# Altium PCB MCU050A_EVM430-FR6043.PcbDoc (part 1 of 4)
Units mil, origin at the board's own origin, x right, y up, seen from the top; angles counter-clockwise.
Board outline 6000 x 4000 mil, 4 copper layers (Top Layer, GND, PWR, Bottom Layer), stack 61.2 mil thick; 337 components, 255 nets, 1099 pads, 437 vias.
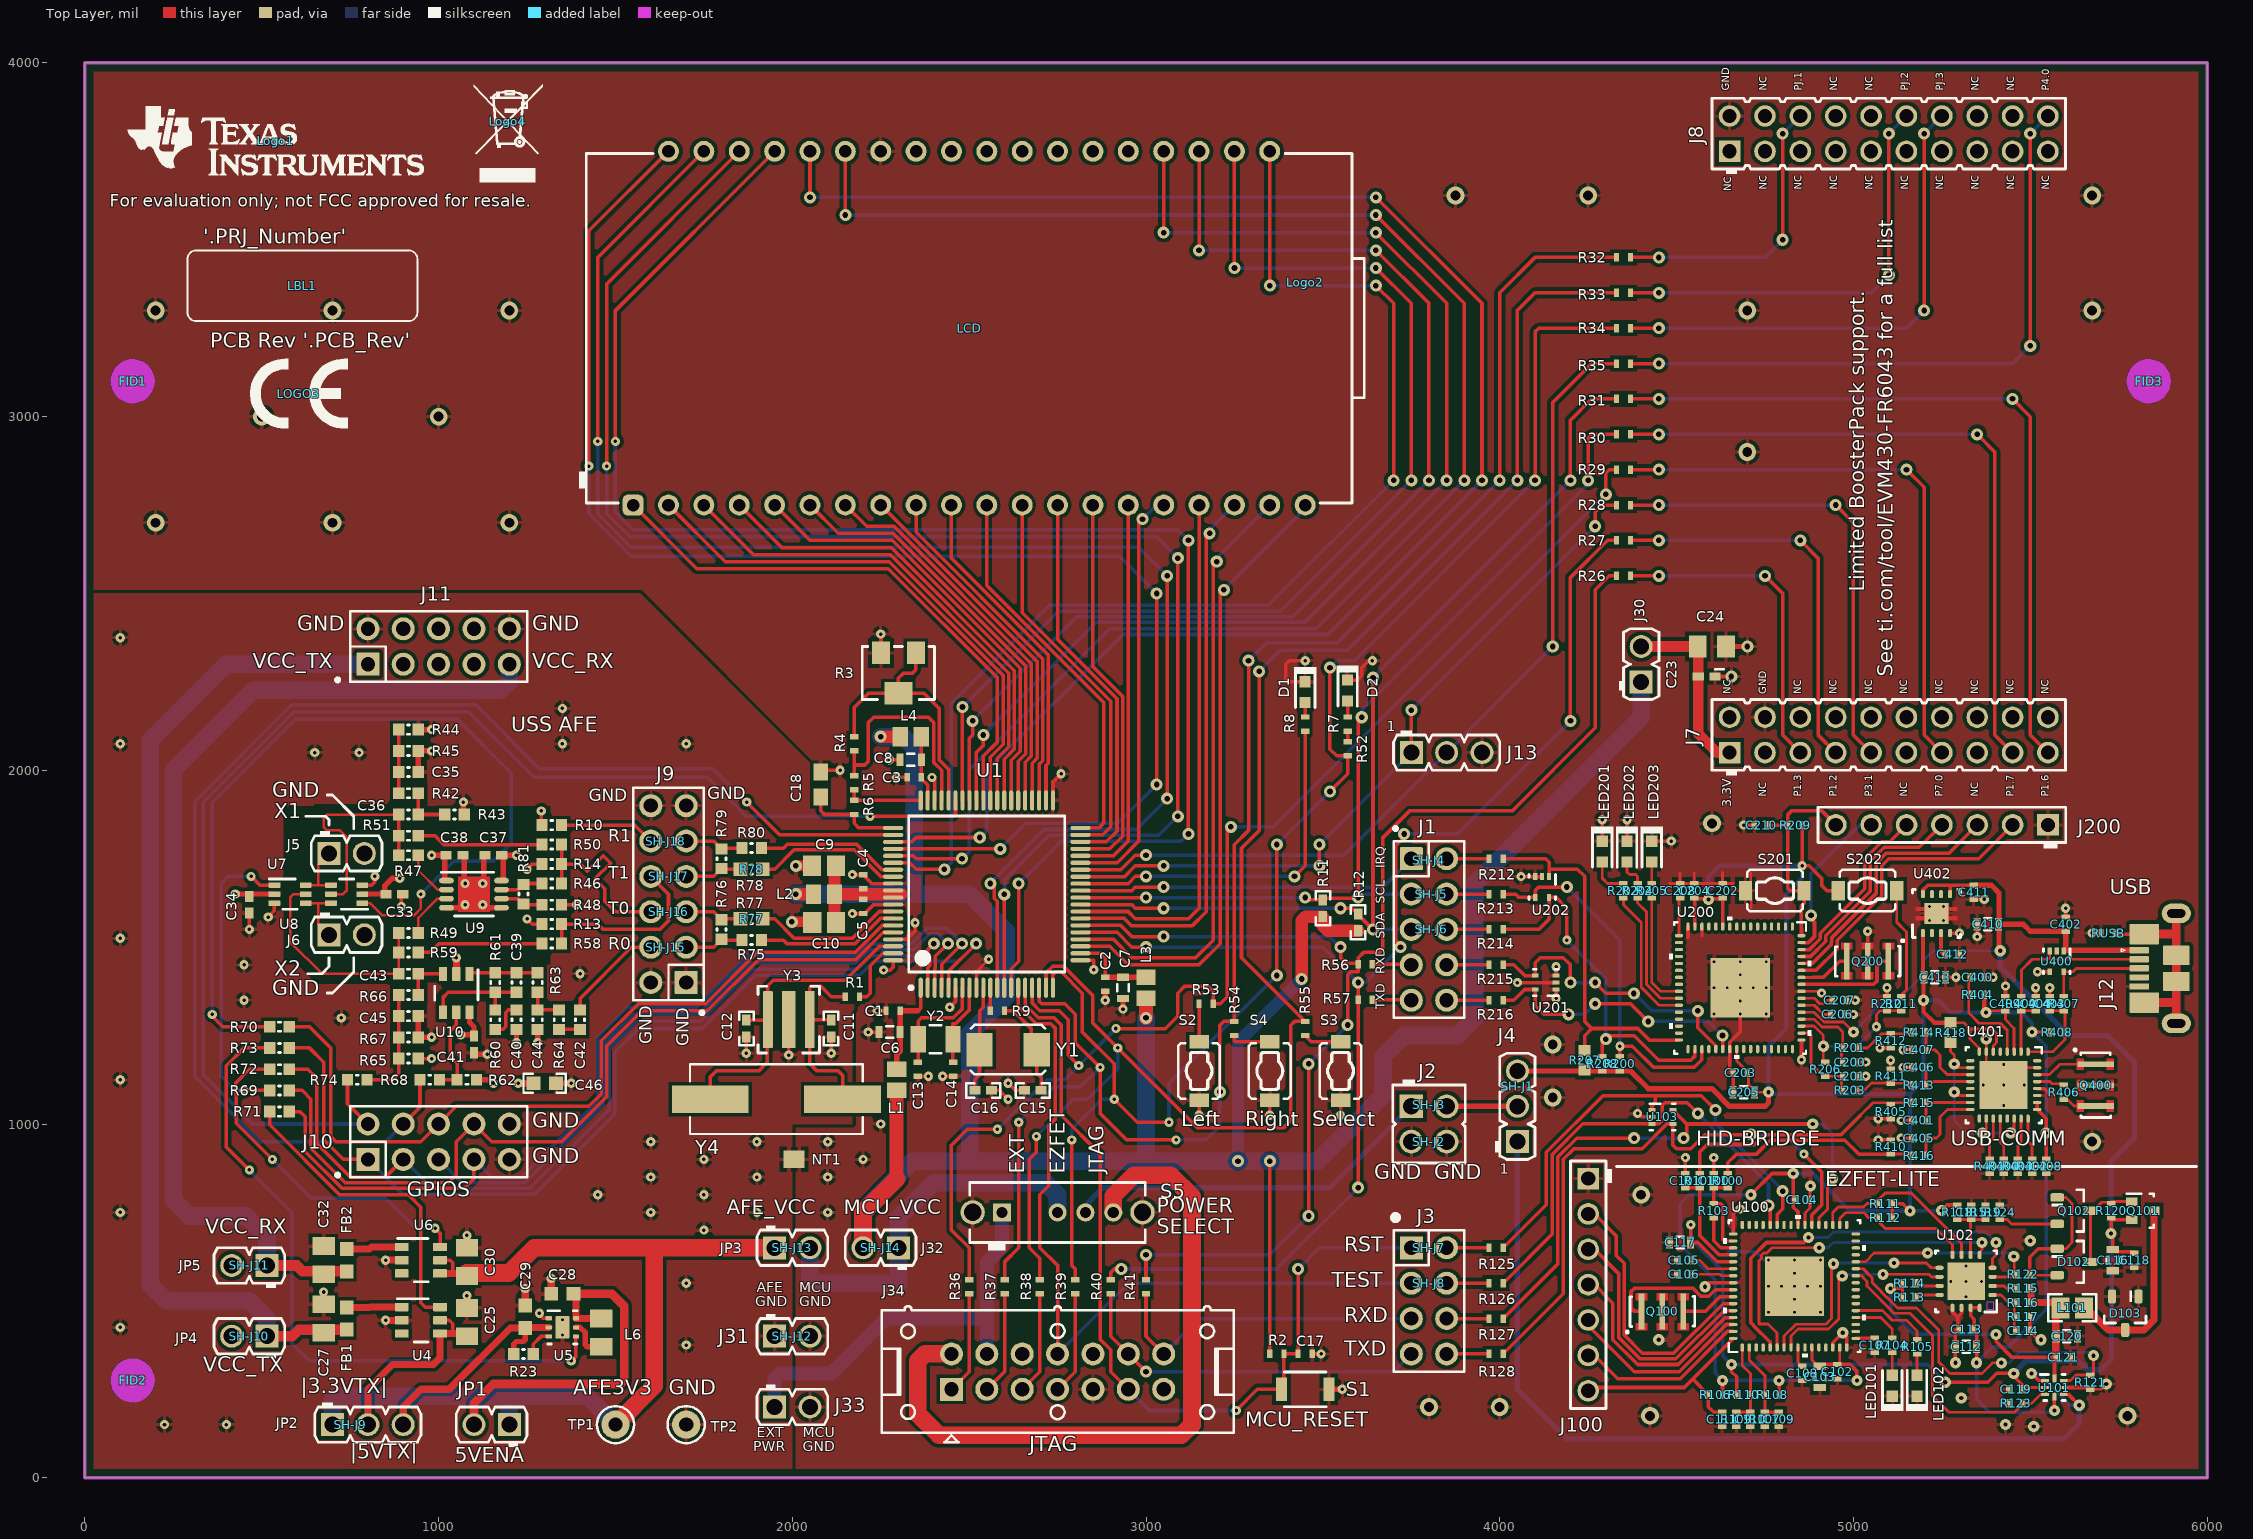
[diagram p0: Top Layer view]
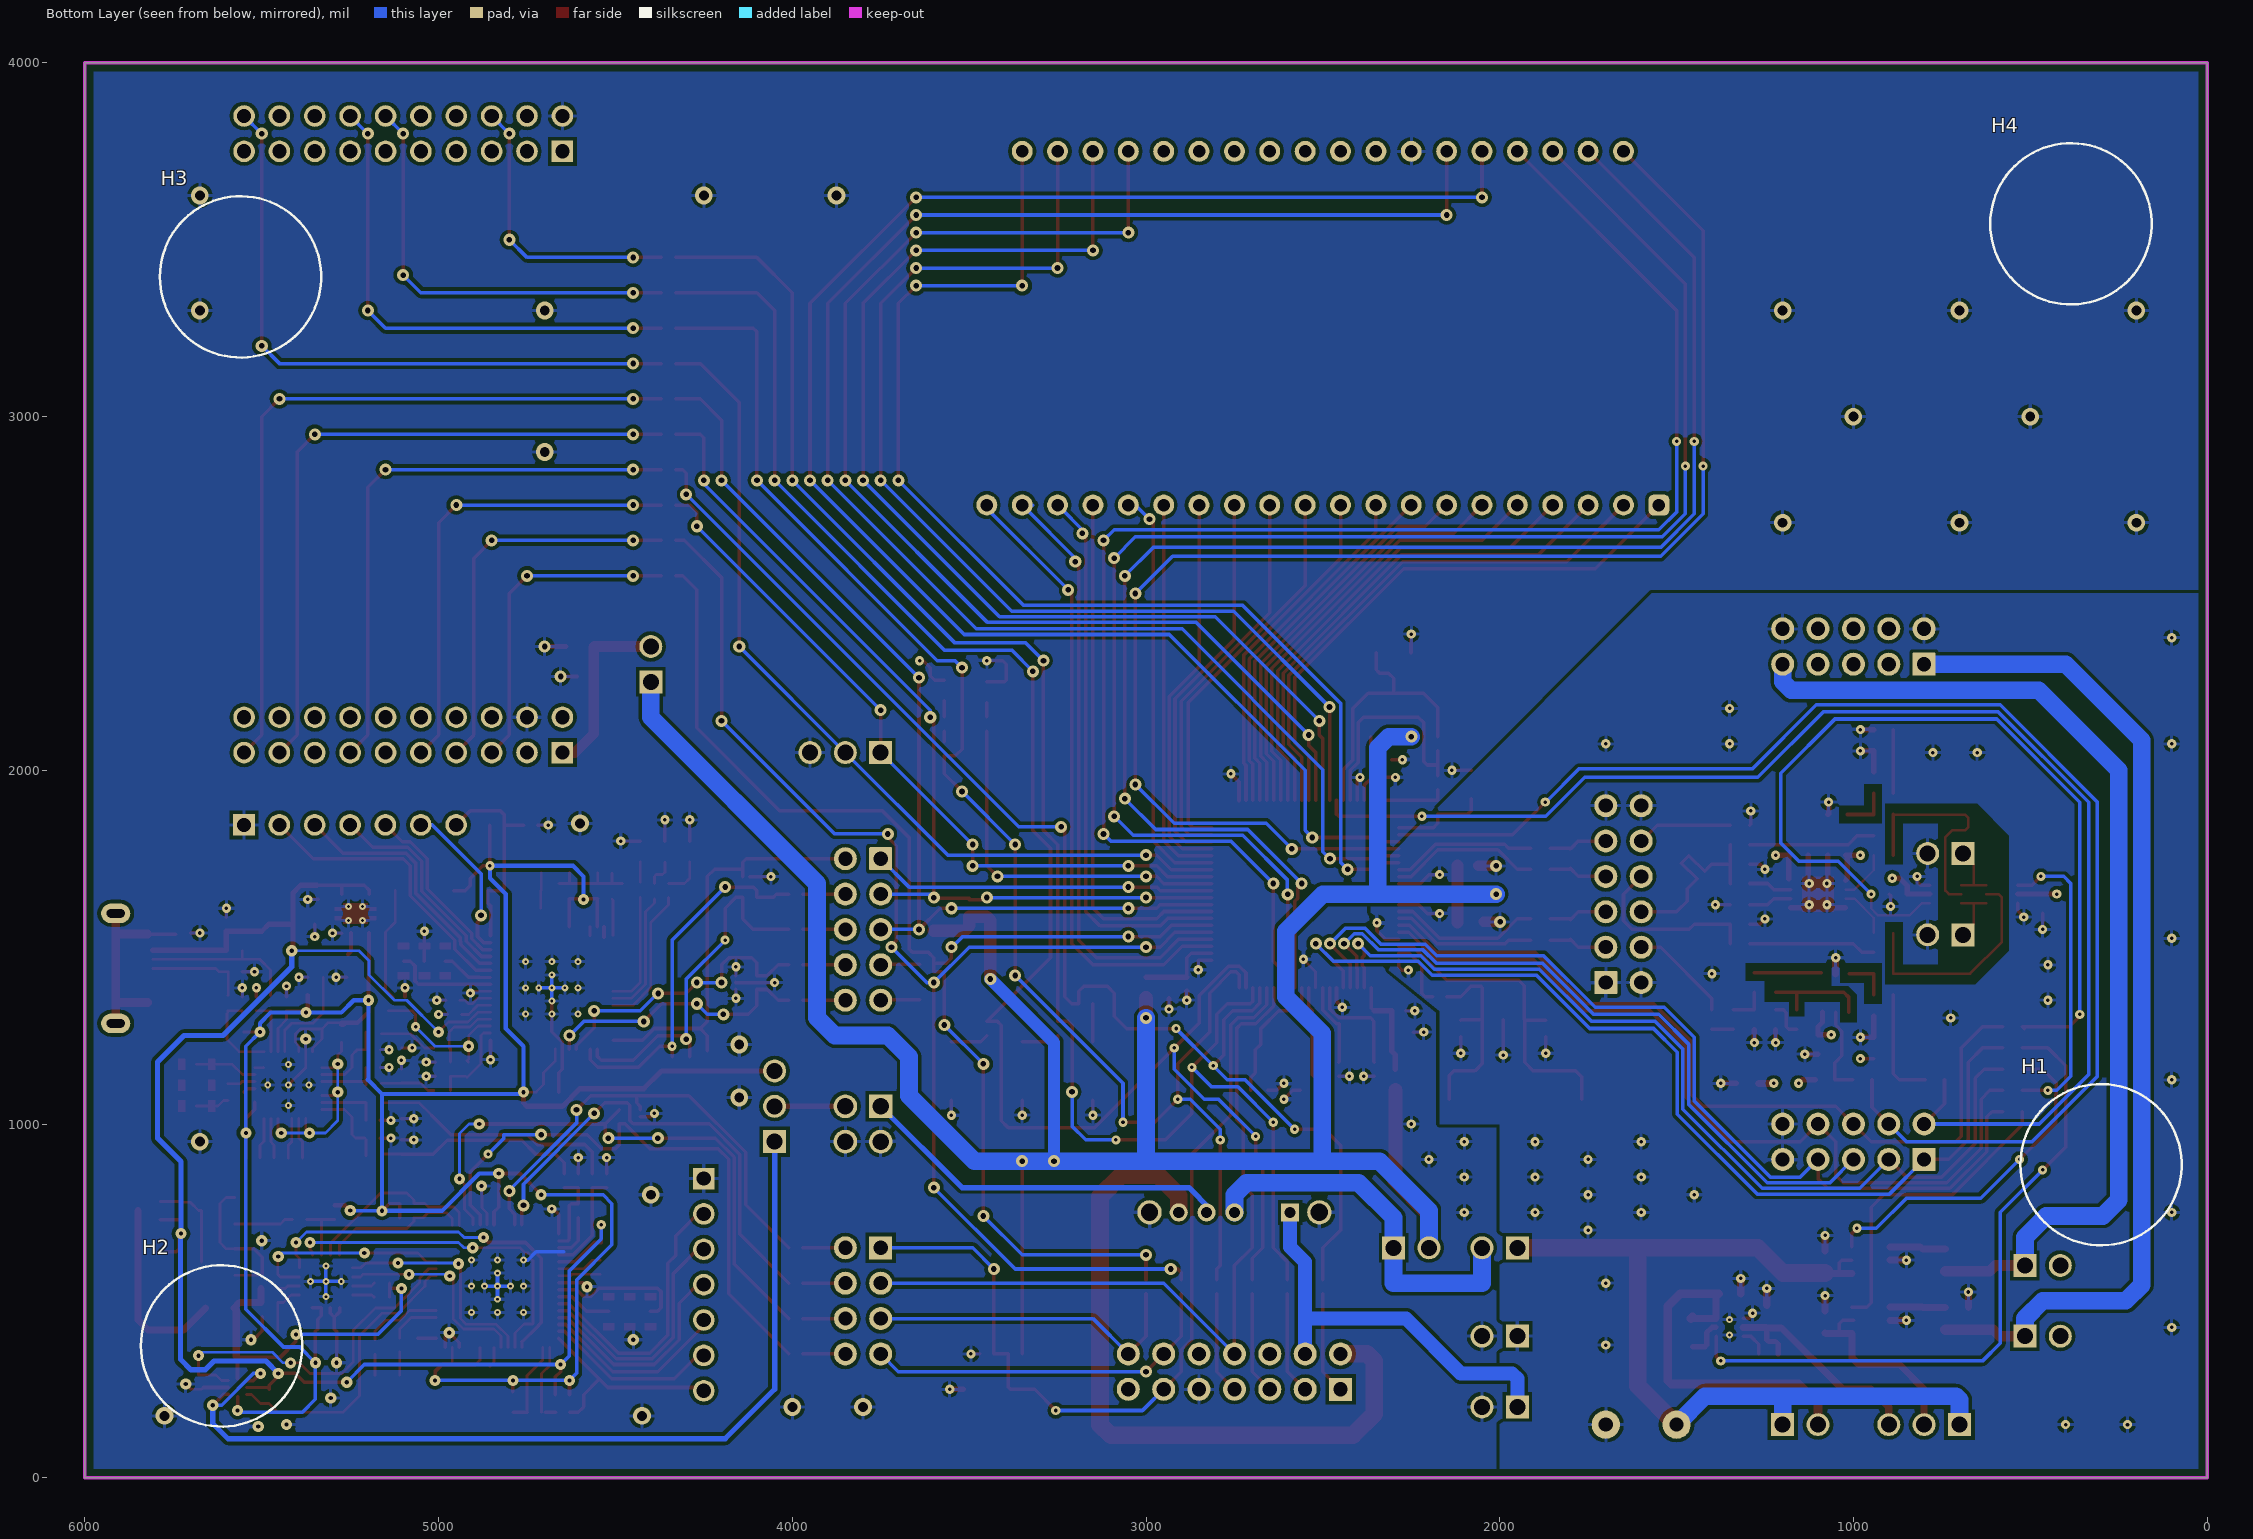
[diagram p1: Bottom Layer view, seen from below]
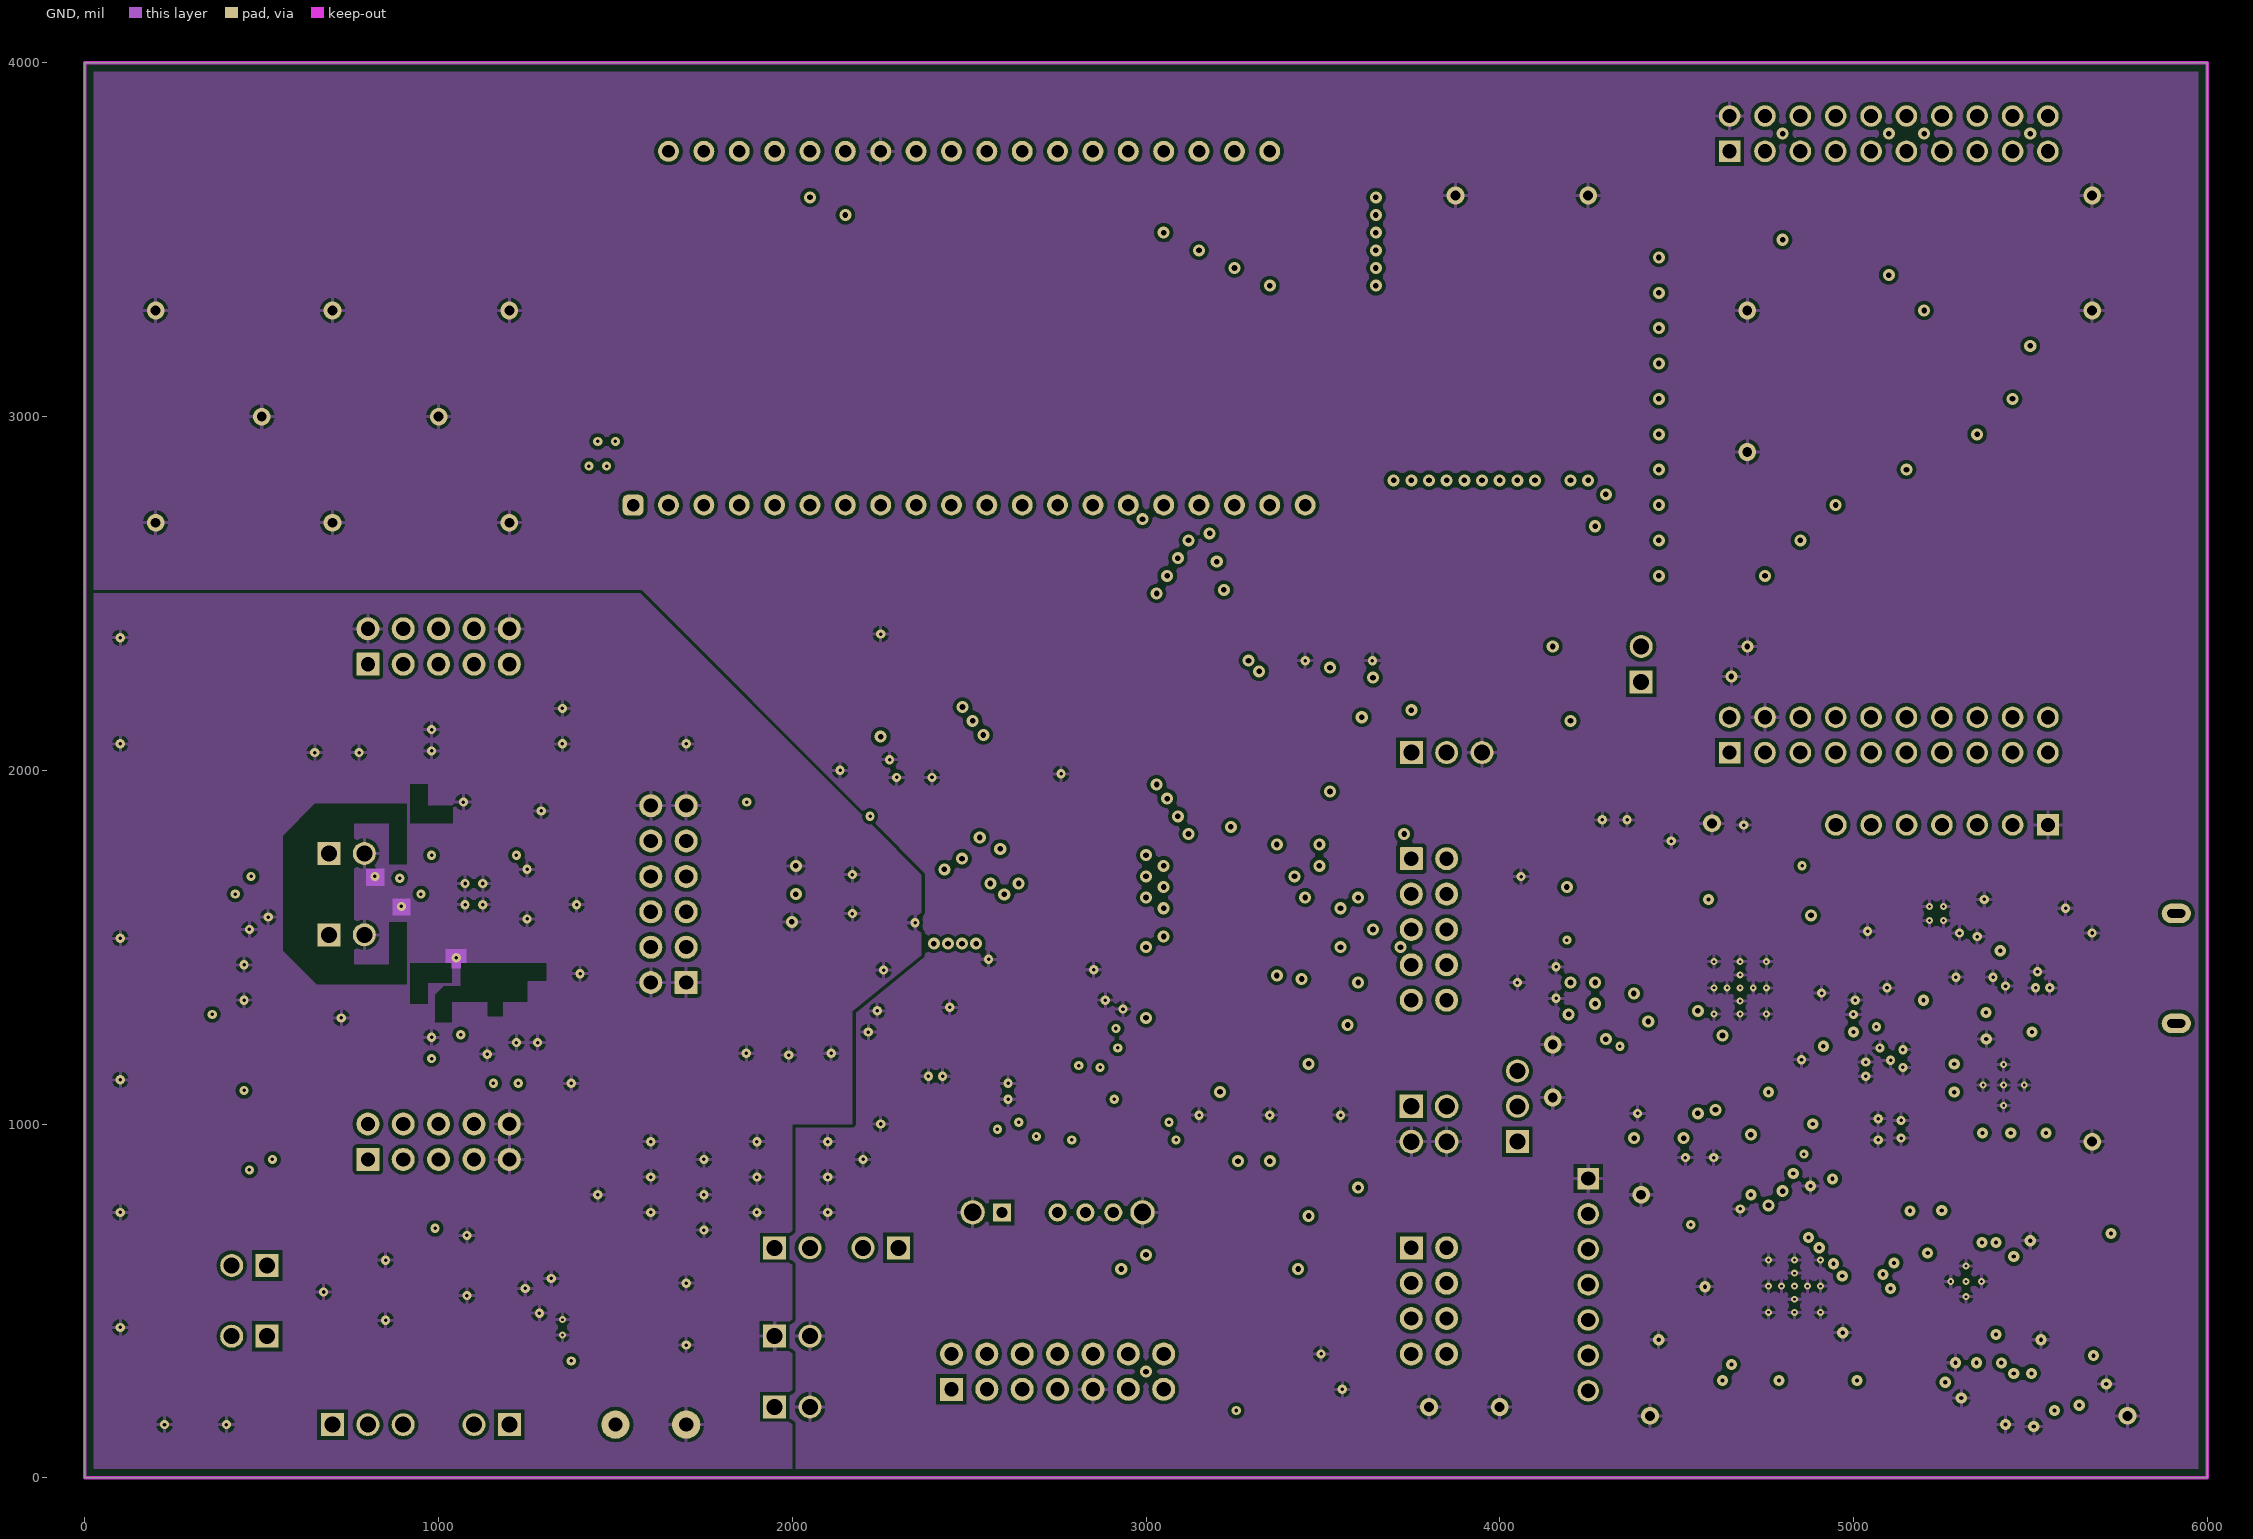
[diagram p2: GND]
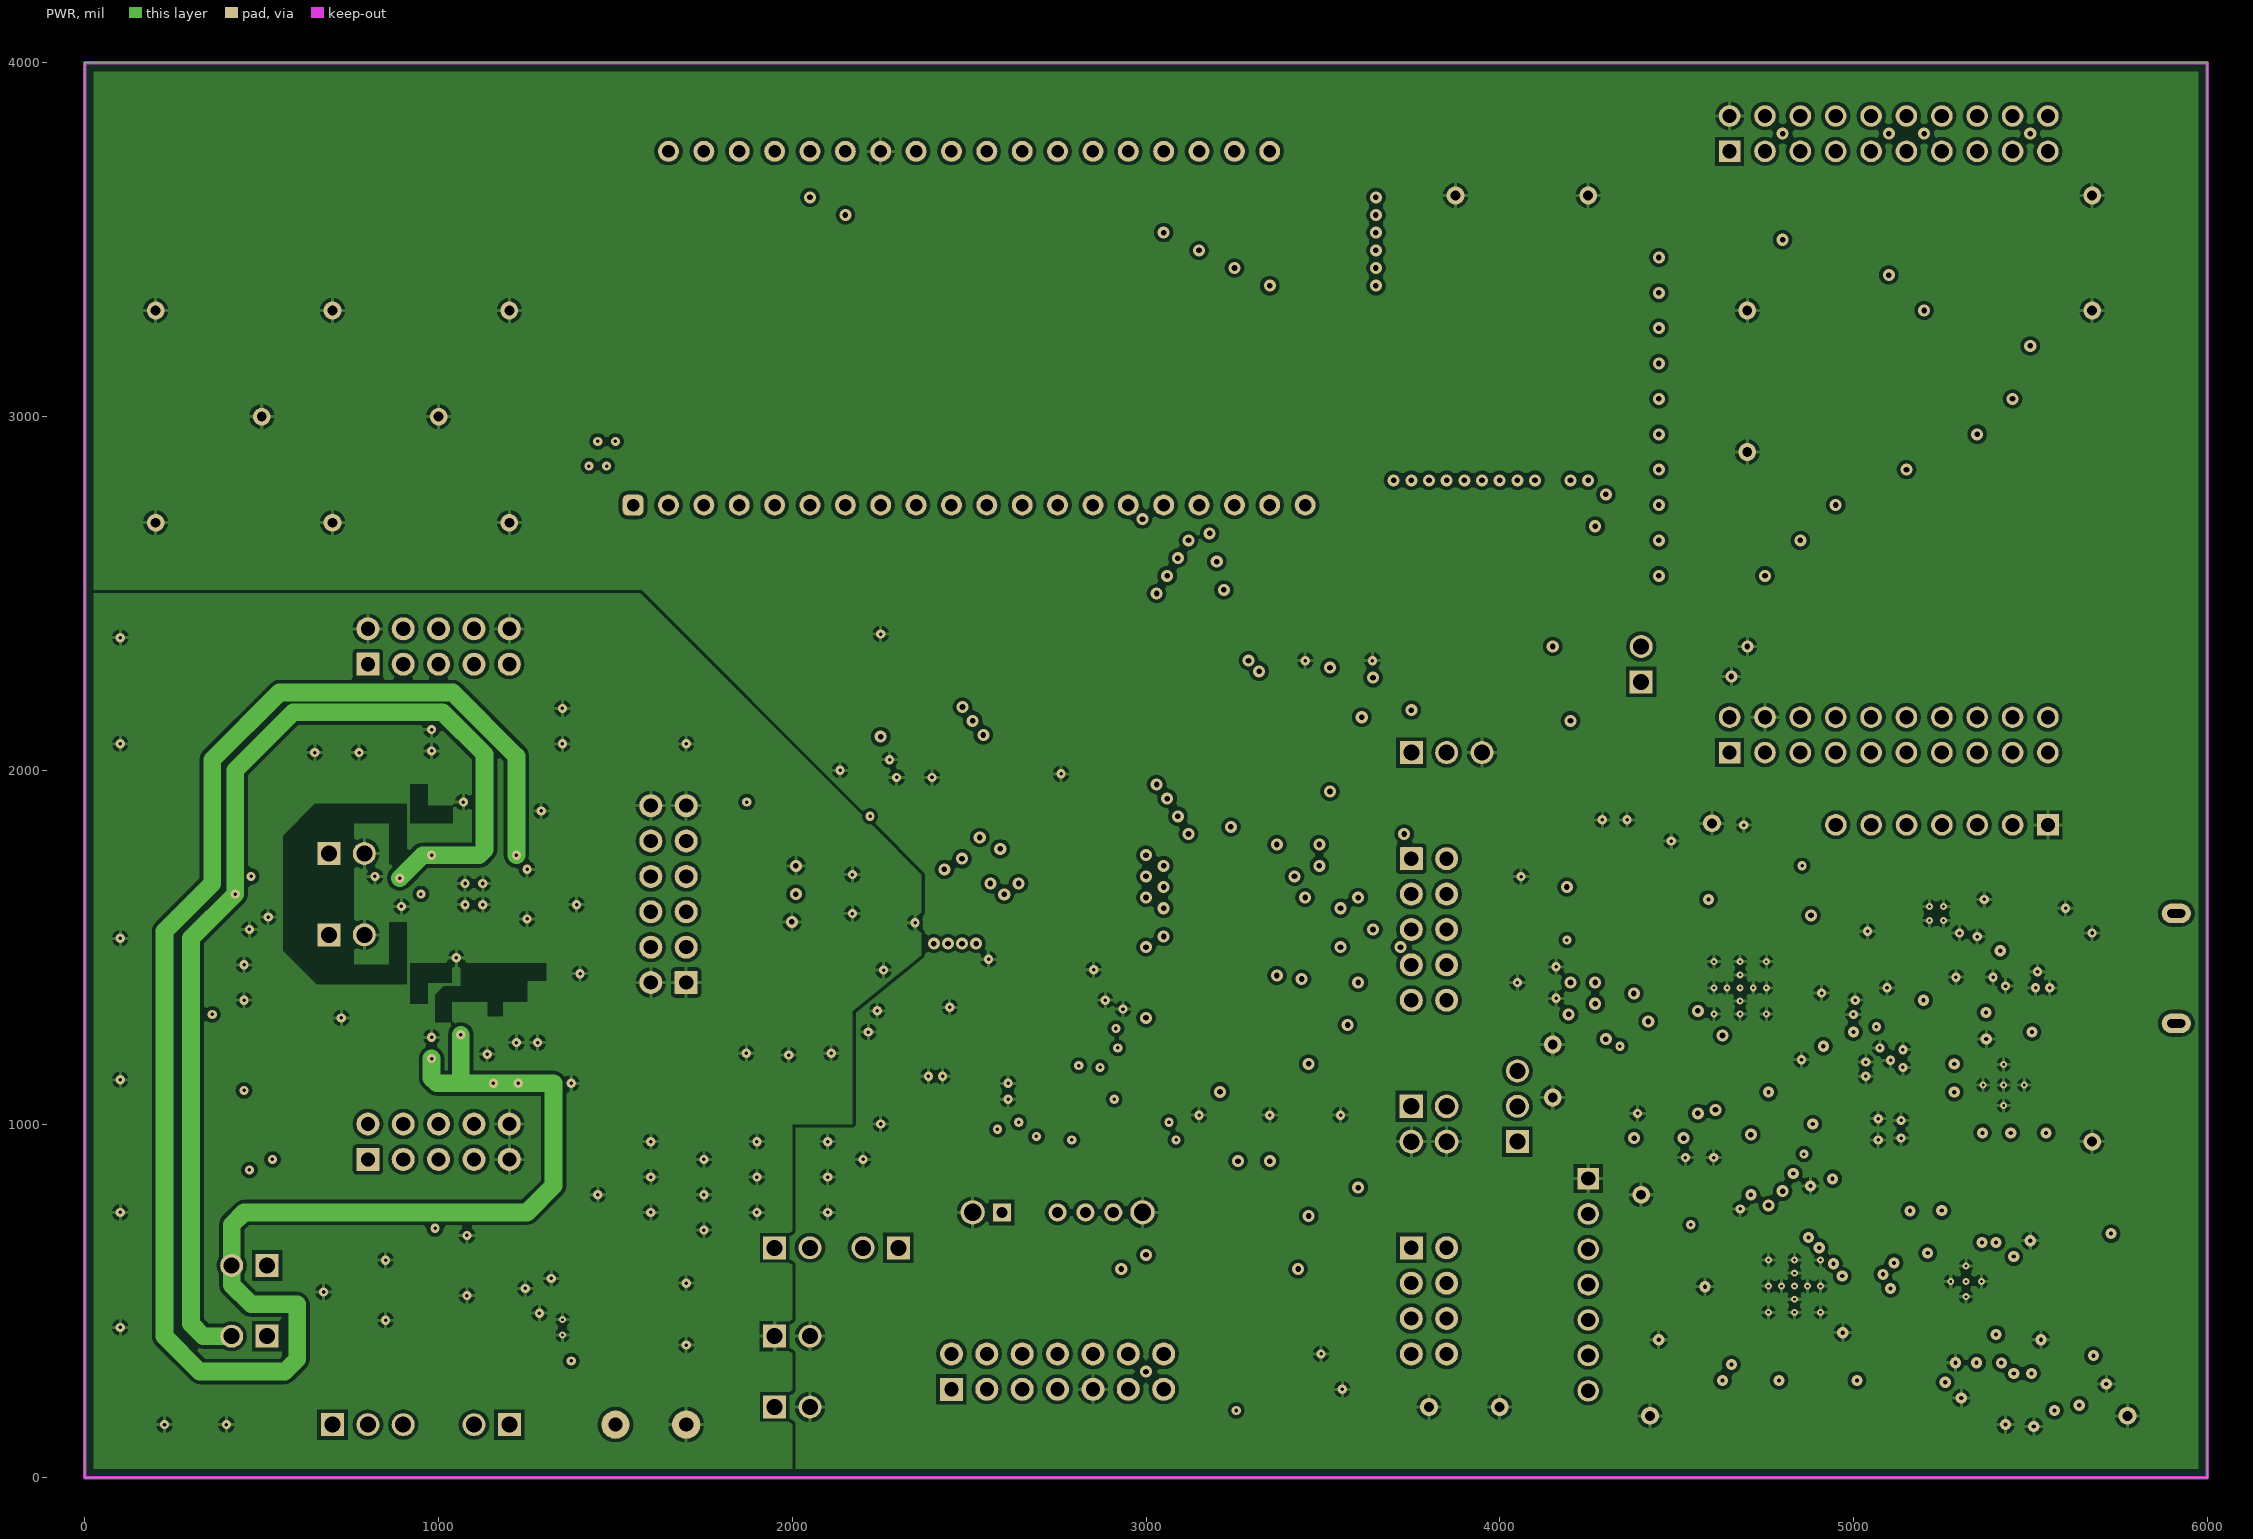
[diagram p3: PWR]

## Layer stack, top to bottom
Top Solder: solder mask 0.4, Solder Resist, Dk 3.5
Top Layer: signal copper 1.4
Dielectric1: core 4.4, FR-4, Dk 4.2
GND: signal copper 0.7
Dielectric 2: core 48.2, FR-4, Dk 4.2
PWR: signal copper 0.7
Dielectric 3: core 4.4, FR-4, Dk 4.2
Bottom Layer: signal copper 1.4
Bottom Solder: solder mask 0.4, Solder Resist, Dk 3.5

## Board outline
0,0 6000,0 6000,4000 0,4000

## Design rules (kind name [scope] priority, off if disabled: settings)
AcuteAngle [All] p1: minimum=4.50000000000000E+0001 checktracksonly=TRUE
AssemblyTestPointUsage [All] p1: valid=2
BoardOutlineClearance BoardOutlineClearance_MountingHoles [OnCopper and InComponentClass('Mounting Holes')] p1: gap=40 ignorepadtopadclearanceinfootprint=FALSE
BoardOutlineClearance BoardOutlineClearance_Poly [OnCopper and IsPoly] p2: gap=25 ignorepadtopadclearanceinfootprint=FALSE
BoardOutlineClearance [OnCopper and Not InComponentClass('Logo') and not InComponentClass('FiducialMark') and not InRegion(1000,500,4000,800) and not InPoly] p3: gap=75 ignorepadtopadclearanceinfootprint=FALSE except(45: SMDPad-OutlineEdge THPad-OutlineEdge; 70: Track-OutlineEdge)
Clearance Clearance_Fiducial [HasFootprint('Fiducial10-30')] p1: gap=0 ignorepadtopadclearanceinfootprint=FALSE
Clearance Clearance_12 [InNamedPolygon('TOP_LAYER_TARGET_GND_P004')] p2: gap=8 ignorepadtopadclearanceinfootprint=FALSE except(0: Arc-Hole Track-Hole SMDPad-Hole THPad-Hole Via-Hole Fill-Hole Poly-Hole Region-Hole Text-Hole)
Clearance Clearance_11 [InNamedPolygon('TOP_LAYER_TARGET_GND_P004')] p3: gap=8 ignorepadtopadclearanceinfootprint=FALSE except(0: Arc-Hole Track-Hole SMDPad-Hole THPad-Hole Via-Hole Fill-Hole Poly-Hole Region-Hole Text-Hole)
Clearance Clearance_10 [InNamedPolygon('TOP_LAYER_TARGET_GND_P004')] p4: gap=8 ignorepadtopadclearanceinfootprint=FALSE except(0: Arc-Hole Track-Hole SMDPad-Hole THPad-Hole Via-Hole Fill-Hole Poly-Hole Region-Hole Text-Hole)
Clearance Clearance_9 [InNamedPolygon('TOP_LAYER_TARGET_GND_P004')] p5: gap=8 ignorepadtopadclearanceinfootprint=FALSE except(0: Arc-Hole Track-Hole SMDPad-Hole THPad-Hole Via-Hole Fill-Hole Poly-Hole Region-Hole Text-Hole)
Clearance Clearance_8 [InNamedPolygon('TOP_LAYER_TARGET_GND_P004')] p6: gap=8 ignorepadtopadclearanceinfootprint=FALSE except(0: Arc-Hole Track-Hole SMDPad-Hole THPad-Hole Via-Hole Fill-Hole Poly-Hole Region-Hole Text-Hole)
Clearance Clearance_7 [InNamedPolygon('TOP_LAYER_TARGET_GND_P004')] p7: gap=10 ignorepadtopadclearanceinfootprint=FALSE except(0: Arc-Hole Track-Hole SMDPad-Hole THPad-Hole Via-Hole Fill-Hole Poly-Hole Region-Hole Text-Hole)
Clearance Clearance_6 [InNamedPolygon('TOP_LAYER_USS_GND_P002')] p8: gap=8 ignorepadtopadclearanceinfootprint=FALSE except(0: Arc-Hole Track-Hole SMDPad-Hole THPad-Hole Via-Hole Fill-Hole Poly-Hole Region-Hole Text-Hole)
Clearance Clearance_5 [InNamedPolygon('BOTTOM_LAYER_USS_GND_P000')] p9: gap=8 ignorepadtopadclearanceinfootprint=FALSE except(0: Arc-Hole Track-Hole SMDPad-Hole THPad-Hole Via-Hole Fill-Hole Poly-Hole Region-Hole Text-Hole)
Clearance Clearance_4 [InNamedPolygon('TARGET_GND_BL')] p10: gap=10 ignorepadtopadclearanceinfootprint=FALSE except(0: Arc-Hole Track-Hole SMDPad-Hole THPad-Hole Via-Hole Fill-Hole Poly-Hole Region-Hole Text-Hole)
Clearance Clearance_3 [InNamedPolygon('TARGET_GND_TL')] p11: gap=10 ignorepadtopadclearanceinfootprint=FALSE except(0: Arc-Hole Track-Hole SMDPad-Hole THPad-Hole Via-Hole Fill-Hole Poly-Hole Region-Hole Text-Hole)
Clearance Clearance_2 [InNamedPolygon('TARGET_GND_BL')] p12: gap=6 ignorepadtopadclearanceinfootprint=FALSE except(0: Arc-Hole Track-Hole SMDPad-Hole THPad-Hole Via-Hole Fill-Hole Poly-Hole Region-Hole Text-Hole)
Clearance Clearance_1 [InNamedPolygon('TARGET_GND_BL')] p13: gap=10 ignorepadtopadclearanceinfootprint=FALSE except(0: Arc-Hole Track-Hole SMDPad-Hole THPad-Hole Via-Hole Fill-Hole Poly-Hole Region-Hole Text-Hole)
Clearance Clearance_Keepouts [((IsTrack Or IsArc) And Not InPoly) And IsFree and IsKeepOut vs ((IsTrack Or IsArc) And Not InPoly) And IsFree and IsKeepOut] p14: gap=0 ignorepadtopadclearanceinfootprint=FALSE
Clearance Clearance_Poly [InPolygon] p15: gap=10 ignorepadtopadclearanceinfootprint=FALSE except(0: Arc-Hole Track-Hole SMDPad-Hole THPad-Hole Via-Hole Fill-Hole Poly-Hole Region-Hole Text-Hole)
Clearance [All] p16: gap=6 ignorepadtopadclearanceinfootprint=FALSE except(0: Arc-Hole Track-Hole SMDPad-Hole THPad-Hole Via-Hole Fill-Hole Poly-Hole Region-Hole Text-Hole)
ComponentClearance ComponentClearance_Shunt_Shunt [InComponentClass('Shunt') vs InComponentClass('Shunt')] p1: gap=0 collisioncheckmode=3 verticalgap=0 showdistances=FALSE
ComponentClearance ComponentClearance_MountingHoles_FiducialMarks [InComponentClass('Mounting Holes') vs InComponentClass('FiducialMark')] p2: gap=50 collisioncheckmode=3 verticalgap=10 showdistances=FALSE
ComponentClearance ComponentClearance_Shunt [InComponentClass('Header') vs InComponentClass('Shunt')] p3: gap=0 collisioncheckmode=3 verticalgap=0 showdistances=FALSE
ComponentClearance ComponentClearance_Logo [InComponentClass('Logo')] p4: gap=50 collisioncheckmode=3 verticalgap=10 showdistances=FALSE
ComponentClearance ComponentClearance_ScrewToNut [(HasFootprint('NY PMS 440 0025 PH')) vs (HasFootprint('Keystone_1902C'))] p5: gap=5 collisioncheckmode=3 verticalgap=10 showdistances=FALSE
ComponentClearance ComponentClearance_MountingHoles [InComponentClass('Mounting Holes')] p6: gap=250 collisioncheckmode=3 verticalgap=100000 showdistances=FALSE
ComponentClearance ComponentClearance_SmallPassives [HasFootprint('0201*') or HasFootprint('0402*') or HasFootprint('0508') or HasFootprint('0603*') or HasFootprint('0612') or HasFootprint('0805*') or HasFootprint('0815*') or HasFootprint('0830*') or HasFootprint('1206*') or HasFootprint('1210*') or HasFootprint('1808*') or HasFootprint('1812*') or HasFootprint('1825*') or HasFootprint('2010*') or HasFootprint('2220*') or HasFootprint('2225*') or HasFootprint('2512*') or HasFootprint('2728*') or HasFootprint('3518*') vs HasFootprint('0201*') or HasFootprint('0402*') or HasFootprint('0508') or HasFootprint('0603*') or HasFootprint('0612') or HasFootprint('0805*') or HasFootprint('0815*') or HasFootprint('0830*') or HasFootprint('1206*') or HasFootprint('1210*') or HasFootprint('1808*') or HasFootprint('1812*') or HasFootprint('1825*') or HasFootprint('2010*') or HasFootprint('2220*') or HasFootprint('2225*') or HasFootprint('2512*') or HasFootprint('2728*') or HasFootprint('3518*')] p7: gap=14.96 collisioncheckmode=3 verticalgap=10 showdistances=FALSE
ComponentClearance ComponentClearance_THtoSMT [IsThruComponent vs IsSMTComponent] p8: gap=25 collisioncheckmode=3 verticalgap=30 showdistances=FALSE
ComponentClearance ComponentClearance_THtoTH [IsThruComponent vs IsThruComponent] p9: gap=30 collisioncheckmode=3 verticalgap=30 showdistances=FALSE
ComponentClearance [All] p10: gap=30 collisioncheckmode=3 verticalgap=10 showdistances=FALSE
DiffPairsRouting [All] p1: maxlimit=100 minlimit=10 mostfreqgap=10 toplayer_minwidth=15 toplayer_maxwidth=15 toplayer_prefwidth=15 midlayer1_minwidth=15 midlayer1_maxwidth=15 midlayer1_prefwidth=15 midlayer2_minwidth=15 midlayer2_maxwidth=15 midlayer2_prefwidth=15 bottomlayer_minwidth=15 bottomlayer_maxwidth=15 bottomlayer_prefwidth=15 maxuncoupledlength=1000
FabricationTestPointUsage TestPointUsage [All] p1: valid=2 allowmultiple=FALSE
FabricationTestpoint Testpoint [All] p1: side=3 testpointundercomponent=TRUE minsize=40 maxsize=100 preferedsize=60 minholesize=0 maxholesize=40 preferedholesize=32 testpointgrid=1 allowsidetop=TRUE allowsidebottom=TRUE usegrid=TRUE gridtolerance=0.01
FanoutControl Fanout_LCC [IsLCC] p1: bgadir=Out bgaviamode=Centered fanoutstyle=Auto fanoutdirection=Alternating viagrid=1 // Fanout_LCC (Default Rule)
FanoutControl Fanout_BGA [IsBGA] p2: bgadir=Out bgaviamode=Centered fanoutstyle=Auto fanoutdirection=Alternating viagrid=1 // Fanout_BGA (Default Rule)
FanoutControl Fanout_Default [All] p4: bgadir=Out bgaviamode=Centered fanoutstyle=Auto fanoutdirection=Alternating viagrid=1 // Fanout_Default (Default Rule)
FanoutControl Fanout_Small [(CompPinCount < 5)] p5: bgadir=Out bgaviamode=Centered fanoutstyle=Auto fanoutdirection=OutThenIn viagrid=1 // Fanout_Small (Default Rule)
HoleSize [All] p1: absolutevalues=TRUE maxlimit=251 minlimit=7.87 maxpercent=80.000 minpercent=20.000
MinimumAnnularRing MinimumAnnularRing_ThermalPadVias [IsVia and InAnyComponent] p1: minimumring=5.91
MinimumAnnularRing [All] p2: minimumring=8
MinimumSolderMaskSliver MinimumSolderMaskSliver_Logo [InComponentClass('Logo') vs InComponentClass('Logo')] p1: minsoldermaskwidth=0.7
MinimumSolderMaskSliver [All] p2: minsoldermaskwidth=3
PlaneConnect [All] p1: planeconnectstyle=Relief reliefexpansion=10 reliefentries=4 reliefconductorwidth=10 reliefairgap=10
PolygonConnect [All] p1: connectstyle=Relief reliefconductorwidth=10 reliefentries=4 polygonreliefangle="90 Angle" airgapwidth=10
RoutingVias ThermalPadVias [IsVia and InAnyComponent] p1: holewidth=7.87 width=19.68 viastyle="Through Hole" minholewidth=7.87 minwidth=19.68 maxholewidth=12.99 maxwidth=23.62
RoutingVias [All] p2: holewidth=16 width=34 viastyle="Through Hole" minholewidth=7.87 minwidth=26 maxholewidth=40 maxwidth=65
SilkToBoardRegionClearance [Not ((IsComment or IsDesignator) And (Hide <> 'False')) and not InRegion(1000,500,4000,800)] p1:
SilkToSilkClearance SilkToSilkClearance_Pb-FreeLogo [(HasFootprint('Pb-Free_Overlay_Medium') OR HasFootprint('Pb-Free_Overlay_Small')) vs (HasFootprint('Pb-Free_Overlay_Medium') OR HasFootprint('Pb-Free_Overlay_Small'))] p1: silktosilkclearance=0
SilkToSilkClearance [All] p2: silktosilkclearance=4
SilkToSolderMaskClearance SilkToComponentPadClearance [(IsPad or IsFill or IsRegion) and InAnycomponent] p1: minsilkscreentomaskgap=3 clearancetoexposedcopper=TRUE
SilkToSolderMaskClearance "Silk to Solder Mask Opening" [All] p2: minsilkscreentomaskgap=4 clearancetoexposedcopper=FALSE
SolderMaskExpansion [All] p1: expansion=1.97
Width PWR [InNetClass('Power_Nets')] p1: maxlimit=50 minlimit=8 preferedwidth=10 midlayer1_minwidth=10 midlayer1_maxwidth=10 midlayer2_minwidth=10 midlayer2_maxwidth=10 minimp=50.000000 maximp=50.000000 favimp=50.000000
Width [All] p2: maxlimit=100 minlimit=6 preferedwidth=10 checkconnectedcopper=TRUE
15 further rules are at their usual default settings.

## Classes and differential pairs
component class FiducialMark: FID1 FID2 FID3
component class Shunt: SH-10 SH-J1 SH-J2 SH-J3 SH-J4 SH-J5 SH-J6 SH-J7 SH-J8 SH-J9 SH-J10 SH-J11 SH-J12 SH-J13 SH-J14 SH-J15 SH-J16 SH-J17 SH-J18
component class AFE: 6 C25 C27 C28 C29 C30 C32 C33 C34 C35 C36 C37 C38 C39 C40 C41 C42 C43 C44 C45 C46 FB1 FB2 J5 J6 J9 J10 J11 JP1 JP2 JP3 JP4 JP5 L6 R10 R13 R14 R23 R42 R43 R44 R45 R46 R47 R48 R49 R50 R51 R58 R59 R60 R61 R62 R63 R64 R65 R66 R67 R68 R69 R70 R71 R72 R73 R74 R75 R76 R77 R78 R79 R80 R81 TP1 TP2 U4 U5 U6 U7 U8 U9 U10
net class Power_Nets: BOOSTER_VCC EXT_VCC EZ-FET_VCC EZFET_TARGET_VCC EZFET_VCCTARGET JTAG_VCC MCU_VCC TARGET_VCC USB_LDO USB_VBUS
component class Logo: Logo1
component class U_EVM430-FR6043_HW: FID1 FID2 FID3 H1 H2 H3 H4 LBL1 Logo1 Logo2 LOGO3 Logo3 Logo4 SH-J1 SH-J2 SH-J3 SH-J4 SH-J5 SH-J6 SH-J7 SH-J8 SH-J9 SH-J10 SH-J11 SH-J12 SH-J13 SH-J14 SH-J15 SH-J16 SH-J17 SH-J18 ZZ1 ZZ2 ZZ3 ZZ4
component class AssemblyNote: ZZ1 ZZ2 ZZ3 ZZ4
component class MCU050A_EVM430-FR6043: J1 J2 J3 J4 J12 R125 R126 R127 R128 R212 R213 R214 R215 R216 RUSB
component class ezFET: C100 C101 C102 C103 C104 C105 C106 C107 C108 C109 C110 C111 C112 C113 C114 C115 C116 C117 C118 C119 C120 C121 D102 D103 J100 L101 LED101 LED102 Q100 Q101 Q102 R100 R101 R103 R104 R105 R106 R107 R108 R109 R110 R111 R112 R113 R114 R115 R116 R117 R118 R119 R120 R121 R122 R123 R124 U100 U101 U102 U103
component class Header: J0 J1 J2 J3 J4 J5 J6 J7 J8 J9 J10 J11 J13 J30 J31 J32 J33 J100 J200 JP1 JP2 JP3 JP4 JP5
component class "HID Bridge": C200 C201 C202 C203 C204 C205 C206 C207 C208 C210 J200 LED201 LED202 LED203 Q200 R200 R201 R202 R203 R204 R205 R206 R207 R208 R209 R210 R211 S201 S202 U200 U201 U202
component class Main: C1 C2 C3 C4 C5 C6 C7 C8 C9 C10 C11 C12 C13 C14 C15 C16 C17 C18 C23 C24 D1 D2 J0 J7 J8 J13 J30 J31 J32 J33 J34 L1 L2 L3 L4 LCD NT1 R1 R2 R3 R4 R5 R6 R7 R8 R9 R11 R12 R26 R27 R28 R29 R30 R31 R32 R33 R34 R35 R36 R37 R38 R39 R40 R41 R52 R53 R54 R55 R56 R57 S1 S2 S3 S4 S5 U1 Y1 Y2 Y3 Y4
component class "USB Hub": C400 C401 C402 C403 C404 C405 C406 C407 C408 C409 C410 C411 C412 C413 Q400 R400 R401 R402 R403 R404 R405 R406 R407 R408 R409 R410 R411 R412 R413 R414 R415 R416 R418 U400 U401 U402
component class Label: LBL1

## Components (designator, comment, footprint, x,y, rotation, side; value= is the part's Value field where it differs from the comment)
C1 "GRM155R71C104KA88D" 0402S 2285,1320 r180 top value=0.1uF
C2 "GRM155R71C104KA88D" 0402S 2885,1395 r90 top value=0.1uF
C3 "GRM155R71C104KA88D" 0402S 2345,1980 r180 top value=0.1uF
C4 "GRM1555C1H102JA01D" 0402S 2200,1685 r270 top value=1000pF
C5 "GRM1555C1H102JA01D" 0402S 2200,1615 r270 top value=1000pF
C6 "GRM188R71A105KA61D" 0603S 2275,1260 r180 top value=1uF
C7 "GRM188R71A105KA61D" 0603S 2935,1385 r90 top value=1uF
C8 "GRM188R71A105KA61D" 0603S 2335,2030 r0 top value=1uF
C9 "C2012X5R1A336M125AC" 0805 2089.69,1730 r0 top value=33uF
C10 "C2012X5R1A336M125AC" 0805 2090,1570 r180 top value=33uF
C11 "GRM1555C1H120JA01D" 0402 2110,1270 r270 top value=12pF
C12 "GRM1555C1H120JA01D" 0402 1870,1270 r270 top value=12pF
C13 "GRM1555C1H120JA01D" 0402S 2355,1155 r270 top value=12pF
C14 "GRM1555C1H120JA01D" 0402S 2455,1155 r90 top value=12pF
C15 "GRM1555C1H120JA01D" 0402 2680,1095 r180 top value=12pF
C16 "GRM1555C1H120JA01D" 0402 2540,1095 r0 top value=12pF
C17 "GRM1555C1H102JA01D" 0402S 3450,350 r0 top value=1000pF
C18 "GRM188R61A475MAAJ" 0603M 2080,1960 r90 top value=4.7uF
C23 "GRM155R71C104KA88D" 0402 4585,2265 r0 top value=0.1uF
C24 "GRM21BR60J476ME15L" 0805_HV 4600,2350 r0 top value=47uF
C25 "GRM219R61A106KE44D" 0805_HV 1079.99,440 r90 top value=10uF
C27 "GRM21BR61C105KA01L" 0805_HV 675,450 r90 top value=1uF
C28 "GRM188R61C225KE15D" 0603 1350,520 r180 top value=2.2uF
C29 "GRM188R61C475KAAJ" 0603 1245,455 r90 top value=4.7uF
C30 "GRM219R61A106KE44D" 0805_HV 1080,610 r90 top value=10uF
C32 "GRM21BR61C105KA01L" 0805_HV 675,615 r90 top value=1uF
C33 "GRM155R71C104KA88D" 0402 875,1650 r180 top value=0.1uF
C34 "GRM155R71C104KA88D" 0402 465,1620 r90 top value=0.1uF
C35 "GRM188R61C225KE15D" 0603L 915,1995 r180 top value=2.2uF
C36 "GRM188R71C105KA12D" 0603L 915,1875 r0 top value=1uF
C37 "GRM155R71C104KA88D" 0402 1155,1760 r180 top value=0.1uF
C38 "GRM155R71C104KA88D" 0402 1045,1760 r180 top value=0.1uF
C39 "GRM1885C1H330JA01D" 0603L 1220,1400 r270 top value=33pF
C40 "GRM188R71C105KA12D" 0603L 1220,1295 r90 top value=1uF
C41 "GRM155R71C104KA88D" 0402 1100,1225 r90 top value=0.1uF
C42 "GRM188R71C102KA01D" 0603L 1400,1295 r270 top value=1000pF
C43 "GRM188R71C105KA12D" 0603L 915,1425 r0 top value=1uF
C44 "GRM1885C1H681JA01D" 0603L 1280,1295 r270 top value=680pF
C45 "GRM188R61C225KE15D" 0603L 915,1305 r180 top value=2.2uF
C46 "GRM188R61C225KE15D" 0603 1300,1115 r0 top value=2.2uF
C100 "GRM1555C1H220JA01D" 0402S 4605,840 r90 top value=22pF
C101 "GRM1555C1H220JA01D" 0402S 4525,840 r90 top value=22pF
C102 "GRM155R71C104KA88D" 0402S 4955,300 r270 top value=0.1uF
C103 "GRM188R61A475MAAJ" 0603S 4905,285 r270 top value=4.7uF
C104 "GRM155R71C104KA88D" 0402S 4853.5,786.39 r0 top value=0.1uF
C105 "GRM155R71C224KA12D" 0402S 4520,615 r180 top value=0.22uF
C106 "GRM155R71C224KA12D" 0402S 4520,575 r180 top value=0.22uF
C107 "GRM155R61C474KE01" 0402S 5060,375 r270 top value=0.47uF
C108 "GRM155R71C104KA88D" 0402S 4855,295 r270 top value=0.1uF
C109 "GRM1555C1H330JA01D" 0402S 4789,165 r270 top value=33pF
C110 "GRM1555C1H330JA01D" 0402S 4709,165 r270 top value=33pF
C111 "GRM1555C1H102JA01D" 0402S 4629,165 r270 top value=1000pF
C112 "GRM188R61A475MAAJ" 0603S 5318.5,370 r180 top value=4.7uF
C113 "GRM155R71C104KA88D" 0402S 5318.5,420 r180 top value=0.1uF
C114 "GRM1555C1H330JA01D" 0402S 5478.5,415 r0 top value=33pF
C115 "GRM1555C1H330JA01D" 0402S 5333.5,750 r90 top value=33pF
C116 "GRM188R61A475MAAJ" 0603S 5733.5,615 r270 top value=4.7uF
C117 "GRM188R61A475MAAJ" 0603S 4510,665 r180 top value=4.7uF
C118 "GRM155R71C104KA88D" 0402S 5793.5,615 r270 top value=0.1uF
C119 "GRM155R71C104KA88D" 0402S 5458.5,250 r180 top value=0.1uF
C120 "GRM188R61A475MAAJ" 0603S 5603.5,400 r0 top value=4.7uF
C121 "GRM155R71C104KA88D" 0402S 5593.5,340 r0 top value=0.1uF
C200 "GRM1555C1H220JA01D" 0402S 4990,1175 r0 top value=22pF
C201 "GRM1555C1H220JA01D" 0402S 4990,1135 r0 top value=22pF
C202 "GRM155R71C104KA88D" 0402S 4630,1660 r90 top value=0.1uF
C203 "GRM155R71C104KA88D" 0402S 4680,1145 r180 top value=0.1uF
C204 "GRM155R71C104KA88D" 0402S 4550,1660 r90 top value=0.1uF
C205 "GRM188R61A475MAAJ" 0603S 4690,1090 r180 top value=4.7uF
C206 "GRM155R71C224KA12D" 0402S 4955,1310 r0 top value=0.22uF
C207 "GRM155R71C224KA12D" 0402S 4960,1350 r0 top value=0.22uF
C208 "GRM155R61C474KE01" 0402S 4510,1660 r90 top value=0.47uF
C210 "GRM1555C1H102JA01D" 0402S 4740,1845 r180 top value=1000pF
C400 "GRM155R71C104KA88D" 0402S 5350,1415 r0 top value=0.1uF
C401 "GRM1555C1H100JA01D" 0402S 5185,1010 r180 top value=10pF
C402 "GRM155R71C104KA88D" 0402S 5600,1565 r90 top value=0.1uF
C403 "GRM1555C1H220JA01D" 0402S 5555,1340 r90 top value=22pF
C404 "GRM1555C1H220JA01D" 0402S 5515,1340 r90 top value=22pF
C405 "GRM1555C1H100JA01D" 0402S 5185,960 r180 top value=10pF
C406 "GRM1555C1H100JA01D" 0402S 5185,1160 r180 top value=10pF
C407 "GRM1555C1H100JA01D" 0402S 5185,1210 r180 top value=10pF
C408 "GRM155R71C104KA88D" 0402S 5545,880 r270 top value=0.1uF
C409 "GRM155R71C104KA88D" 0402S 5430,1340 r90 top value=0.1uF
C410 "GRM188R61A106ME69D" 0603S 5380,1565 r180 top value=10uF
C411 "GRM155R71C104KA88D" 0402S 5340,1655 r270 top value=0.1uF
C412 "GRM155R71C103KA01D" 0402S 5280,1480 r0 top value=0.01uF
C413 "GRM188R61A106ME69D" 0603S 5230,1415 r0 top value=10uF
D1 "LTST-C191TGKT" LTST-C191_Green 3450,2220.83 r90 top value=Green
D2 "LTST-C191TGKT" LTST-C191_Green 3570,2225.41 r90 top value=Green
D102 "BAS40-05-7-F" SOT-23 5623.5,610 r0 top value=40V
D103 "BAS40-05-7-F" SOT-23 5768.5,465 r270 top value=40V
FB1 "MPZ1608S221A" 0603 740,450 r270 top value="220 ohm"
FB2 "MPZ1608S221A" 0603 740,615 r270 top value="220 ohm"
FID1 "Fiducial" Fiducial10-30 135,3100 r0 top
FID2 "Fiducial" Fiducial10-30 135,275 r0 top
FID3 "Fiducial" Fiducial10-30 5835,3100 r0 top
H1 "SJ-5303 (CLEAR)" Bumpon_SJ5003Transparent 300,885 r180 bottom
H2 "SJ-5303 (CLEAR)" Bumpon_SJ5003Transparent 5613.5,372.5 r180 bottom
H3 "SJ-5303 (CLEAR)" Bumpon_SJ5003Transparent 5560,3395 r180 bottom
H4 "SJ-5303 (CLEAR)" Bumpon_SJ5003Transparent 385,3545 r180 bottom
J1 "TSW-105-07-G-D" TSW-105-07-G-D 3800,1550 r270 top
J2 "PBC02DAAN" Sullins_PxC02DAAN 3800,1000 r0 top
J3 "PEC04DAAN" CONN_PEC04DAAN 3800,500 r270 top
J4 "61300311121" WURTH_61300311121 4050,1050 r90 top
J5 "61300211121" WURTH_61300211121 740,1765 r0 top
J6 "61300211121" WURTH_61300211121 740,1535 r0 top
J7 "TSW-110-07-T-D" Samtec_TSW-110-07-x-D 5100,2100 r90 top
J8 "TSW-110-07-T-D" Samtec_TSW-110-07-x-D 5100,3800 r90 top
J9 "TSW-106-07-G-D" TSW-106-07-G-D 1650,1650 r90 top locked
J10 "TSW-105-07-G-D" TSW-105-07-G-D 1000,950 r0 top locked
J11 "TSW-105-07-G-D" TSW-105-07-G-D 1000,2350 r0 top locked
J12 "1051640001" Molex_1051640001 5970,1440 r90 top
J13 "61300311121" WURTH_61300311121 3850,2050 r0 top
J30 "61300211121" WURTH_61300211121 4400,2300 r90 top
J31 "61300211121" WURTH_61300211121 2000,400 r0 top
J32 "61300211121" WURTH_61300211121 2250,650 r180 top
J33 "61300211121" WURTH_61300211121 2000,200 r0 top
J34 "SBH11-PBPC-D07-ST-BK" CONN_SBH11-PBPC-D07-ST-BK 2750,300 r0 top
J100 "PBC07SAAN" Sullins_xxC07SAAN 4250.31,545.79 r270 top
J200 "PBC07SAAN" Sullins_xxC07SAAN 5250.31,1845.79 r180 top
JP1 "61300211121" WURTH_61300211121 1150,150 r180 top
JP2 "61300311121" WURTH_61300311121 800,150 r0 top
JP3 "61300211121" WURTH_61300211121 2000,650 r0 top
JP4 "61300211121" WURTH_61300211121 465,400 r180 top
JP5 "61300211121" WURTH_61300211121 465,600 r180 top
L1 "MPZ2012S601A" 0805L 2295,1125 r270 top value="600 ohm"
L2 "MPZ2012S601A" 0805L 2089.69,1650 r0 top value="600 ohm"
L3 "MPZ2012S601A" 0805L 3000,1385 r270 top value="600 ohm"
L4 "MPZ2012S601A" 0805L 2335,2095 r180 top value="600 ohm"
L6 "LQM21PN1R0MC0D" 0805_HV 1460,410 r90 top value=1uH
L101 "CIG21L2R2MNE" 0805 5618.5,480 r180 top value=2.2uH
LBL1 "THT-14-423-10" Label_650x200 615,3370 r180 top
LCD "FH-1138P" ADKOM_FH-1138P 2500,3250 r90 top
LED101 "LTST-C190CKT" LED_LTST-C190_Red 5110,260 r270 top value=Red
LED102 "LTST-C191TGKT" LTST-C191_Green 5180,260 r270 top value=Green
LED201 "LTST-C191TGKT" LTST-C191_Green 4290,1770 r90 top value=Green
LED202 "LTST-C191TGKT" LTST-C191_Green 4360,1770 r90 top value=Green
LED203 "LTST-C190CKT" LED_LTST-C190_Red 4430,1770 r90 top value=Red
Logo1 "Texas Instruments" TI_Stacked_Overlay_Small 540,3780 r0 top
Logo2 "FCC disclaimer" FCC_disclaimer 3450,3380 r0 top
LOGO3 "CE Mark" CE_Mark_5mm 605,3065 r0 top
Logo4 "WEEE logo" WEEE_Minimum 1195,3835 r0 top
NT1 "Net-Tie" Net-Tie_50milWide_30milLong 2005,900 r0 top net-tie
Q100 "CSTCR4M00G15L99-R0" Murata_CSTCR 4460,470 r0 top
Q101 "DMG1013UW" SOT-323 5818.5,755 r0 top value=-50V
Q102 "BC850CLT1G" SOT-23 5623.5,755 r0 top value=0.7V
Q200 "CSTCR4M00G15L99-R0" Murata_CSTCR 5040,1460 r180 top
Q400 "CSTCR6M00G53Z-R0" Murata_CSTCR 5685,1110 r270 top
R1 "CRCW040222R0JNED" 0402S 2170,1360 r0 top value=22
R2 "CRCW040247K0JNED" 0402S 3370,350 r180 top value=47k
R3 "3224W-1-204E" TRIM_3224W 2300,2275 r270 top value=200k
R4 "CRCW0402330KJNED" 0402S 2175,2075 r90 top value=330k
R5 "CRCW0402330KJNED" 0402S 2175,1965 r270 top value=330k
R6 "CRCW0402330KJNED" 0402S 2175,1895 r270 top value=330k
R7 "CRCW0402390RJNED" 0402S 3570,2130.83 r90 top value=390
R8 "CRCW0402390RJNED" 0402S 3450,2130.83 r90 top value=390
R9 "CRCW040222R0JNED" 0402S 2580,1320 r180 top value=22
R10 "RC0603FR-071ML" 0603L 1320,1845 r0 top value=1.00Meg
R11 "ERJ-2RKF3301X" 0402 3500,1610 r270 top value=3.30k
R12 "ERJ-2RKF3301X" 0402 3600,1570 r270 top value=3.30k
R13 "RC0603FR-071ML" 0603L 1320,1565 r0 top value=1.00Meg
R14 "RC0603FR-071ML" 0603L 1320,1735 r0 top value=1.00Meg
R23 "RC0603JR-070RL" 0603L 1240,350 r0 top value=0
R26 "CRCW04020000Z0ED" 0402S 4350,2550 r0 top value=0
R27 "CRCW04020000Z0ED" 0402S 4350,2650 r0 top value=0
R28 "CRCW04020000Z0ED" 0402S 4350,2750 r0 top value=0
R29 "CRCW04020000Z0ED" 0402S 4350,2850 r0 top value=0
R30 "CRCW04020000Z0ED" 0402S 4350,2950 r0 top value=0
R31 "CRCW04020000Z0ED" 0402S 4350,3050 r0 top value=0
R32 "CRCW04020000Z0ED" 0402S 4350,3450 r0 top value=0
R33 "CRCW04020000Z0ED" 0402S 4350,3350 r0 top value=0
R34 "CRCW04020000Z0ED" 0402S 4350,3250 r0 top value=0
R35 "CRCW04020000Z0ED" 0402S 4350,3150 r0 top value=0
R36 "CRCW04020000Z0ED" 0402S 2500,540 r90 top value=0
R37 "CRCW04020000Z0ED" 0402S 2600,540 r90 top value=0
R38 "CRCW04020000Z0ED" 0402S 2700,540 r90 top value=0
R39 "CRCW04020000Z0ED" 0402S 2800,540 r90 top value=0
R40 "CRCW04020000Z0ED" 0402S 2900,540 r90 top value=0
R41 "CRCW04020000Z0ED" 0402S 3000,540 r90 top value=0
R42 "RC0603FR-0724K9L" 0603L 915,1935 r0 top value=24.9k
R43 "RC0603FR-07200KL" 0603L 1045,1875 r0 top value=200k
R44 "RC0603FR-072ML" 0603L 915,2115 r180 top value=2.00Meg
R45 "RC0603FR-072ML" 0603L 915,2055 r180 top value=2.00Meg
R46 "RC0603JR-070RL" 0603L 1320,1680 r180 top value=0
R47 "RC0603FR-07806RL" 0603L 915,1760 r180 top value=806
R48 "RC0603JR-070RL" 0603L 1320,1620 r180 top value=0
R49 "RC0603FR-07806RL" 0603L 915,1540 r180 top value=806
R50 "RC0603JR-070RL" 0603L 1320,1790 r180 top value=0
R51 "RC0603FR-07806RL" 0603L 915,1815 r180 top value=806
R52 "CRCW04020000Z0ED" 0402S 3570,2060.83 r270 top value=0
R53 "CRCW04020000Z0ED" 0402S 3170,1340 r0 top value=0
R54 "CRCW04020000Z0ED" 0402S 3250,1270 r90 top value=0
R55 "CRCW04020000Z0ED" 0402S 3450,1270 r90 top value=0
R56 "CRCW04020000Z0ED" 0402S 3620,1451.79 r180 top value=0
R57 "CRCW04020000Z0ED" 0402S 3620,1351.79 r180 top value=0
R58 "RC0603JR-070RL" 0603L 1320,1510 r180 top value=0
R59 "RC0603FR-07806RL" 0603L 915,1485 r180 top value=806
R60 "RC0603FR-0710RL" 0603L 1160,1295 r90 top value=10.0
R61 "RC0603FR-071K82L" 0603L 1160,1400 r90 top value=1.82k
R62 "RCG060310K0FKEA" 0603L 1080,1125 r180 top value=10.0k
R63 "RC0603FR-07499RL" 0603L 1280,1400 r270 top value=499
R64 "RC0603JR-070RL" 0603L 1340,1295 r90 top value=0
R65 "RC0603FR-072ML" 0603L 915,1185 r0 top value=2.00Meg
R66 "RC0603FR-0724K9L" 0603L 915,1365 r0 top value=24.9k
R67 "RC0603FR-072ML" 0603L 915,1245 r180 top value=2.00Meg
R68 "RC0603JR-070RL" 0603L 975,1125 r180 top value=0
R69 "RC0603JR-070RL" 0603L 550,1095 r180 top value=0
R70 "RC0603JR-070RL" 0603L 550,1275 r0 top value=0
R71 "RC0603JR-070RL" 0603L 550,1035 r0 top value=0
R72 "RC0603JR-070RL" 0603L 550,1155 r0 top value=0
R73 "RC0603JR-070RL" 0603L 550,1215 r0 top value=0
R74 "RC0603JR-070RL" 0603L 770,1125 r180 top value=0
R75 "RC0603JR-070RL" 0603L 1885,1520 r180 top value=0
R76 "RC0603JR-070RL" 0603L 1800,1550 r270 top value=0
R77 "RC0603FR-07200RL" 0603 1885,1580 r180 top value=200
R77 "RC0603JR-070RL" 0603L 1885,1580 r180 top value=0
R78 "RC0603FR-07200RL" 0603 1885,1720 r180 top value=200
R78 "RC0603JR-070RL" 0603L 1885,1720 r180 top value=0
R79 "RC0603JR-070RL" 0603L 1800,1750 r270 top value=0
R80 "RC0603JR-070RL" 0603L 1885,1780 r180 top value=0
R81 "RCG060310K0FKEA" 0603L 1240,1650 r90 top value=10.0k
R100 "CRCW040222R0JNED" 0402S 4645,840 r270 top value=22
R101 "CRCW040222R0JNED" 0402S 4565,840 r270 top value=22
R103 "CRCW04021K50JNED" 0402S 4605,755 r90 top value=1.5k
R104 "CRCW0402470RJNED" 0402S 5110,375 r90 top value=470
R105 "CRCW0402390RJNED" 0402S 5180,370 r90 top value=390
R106 "CRCW040247K0JNED" 0402S 4610,235 r0 top value=47k
R107 "CRCW0402221KFKED" 0402S 4749,165 r90 top value=221k
R108 "CRCW0402221KFKED" 0402S 4770,235 r0 top value=221k
R109 "CRCW0402150KFKED" 0402S 4669,165 r90 top value=150k
R110 "CRCW0402240KFKED" 0402S 4690,235 r180 top value=240k
R111 "CRCW04024K70JNED" 0402S 5090,775 r180 top value=4.7k
R112 "CRCW04024K70JNED" 0402S 5090,735 r180 top value=4.7k
R113 "CRCW04022K20FKED" 0402S 5158.5,510 r180 top value=2.20k
R114 "CRCW04026K81FKED" 0402S 5158.5,550 r180 top value=6.81k
R115 "CRCW04023K32FKED" 0402S 5478.5,535 r180 top value=3.32k
R116 "CRCW0402221KFKED" 0402S 5478.5,495 r0 top value=221k
R117 "CRCW0402221KFKED" 0402S 5478.5,455 r180 top value=221k
R118 "CRCW0402221KFKED" 0402S 5293.5,750 r270 top value=221k
R119 "CRCW0402221KFKED" 0402S 5373.5,750 r270 top value=221k
R120 "CRCW0402470RJNED" 0402S 5728.5,755 r90 top value=470
R121 "CRCW040247K0JNED" 0402S 5670,270 r90 top value=47k
R122 "CRCW0402820RJNED" 0402S 5478.5,575 r180 top value=820
R123 "CRCW040247K0JNED" 0402S 5458.5,210 r0 top value=47k
R124 "CRCW04020000Z0ED" 0402S 5413.5,750 r90 top value=0
R125 "CRCW0402100RJNED" 0402S 3990,650 r180 top value=100
R126 "CRCW0402100RJNED" 0402S 3990,550 r180 top value=100
R127 "CRCW0402100RJNED" 0402S 3990,450 r180 top value=100
R128 "CRCW0402100RJNED" 0402S 3990,350 r180 top value=100
R200 "CRCW04022K20FKED" 0402S 4340,1170 r270 top value=2.20k
R201 "CRCW040222R0JNED" 0402S 4990,1215 r180 top value=22
R202 "CRCW0402390RJNED" 0402S 4350,1660 r270 top value=390
R203 "CRCW040222R0JNED" 0402S 4990,1095 r180 top value=22
R204 "CRCW0402390RJNED" 0402S 4390,1660 r270 top value=390
R205 "CRCW0402470RJNED" 0402S 4430,1660 r270 top value=470
R206 "CRCW04021K50JNED" 0402S 4920,1155 r90 top value=1.5k
R207 "RCG060310K0FKEA" 0603L 4240,1180 r270 top value=10.0k
R208 "CRCW04022K20FKED" 0402S 4290,1170 r270 top value=2.20k
R209 "CRCW040247K0JNED" 0402S 4835,1845 r0 top value=47k
R210 "CRCW04021M00JNED" 0402S 5095,1340 r270 top value=1.0Meg
R211 "CRCW0402100RJNED" 0402S 5135,1340 r90 top value=100
R212 "CRCW0402100RJNED" 0402S 3990,1750 r180 top value=100
R213 "CRCW0402100RJNED" 0402S 3990,1650 r180 top value=100
R214 "CRCW0402100RJNED" 0402S 3990,1550 r180 top value=100
R215 "CRCW0402100RJNED" 0402S 3990,1450 r180 top value=100
R216 "CRCW0402100RJNED" 0402S 3990,1350 r180 top value=100
R400 "CRCW040215K0JNED" 0402S 5425,880 r270 top value=15k
R401 "CRCW040215K0JNED" 0402S 5385,880 r270 top value=15k
R402 "CRCW040215K0JNED" 0402S 5505,880 r270 top value=15k
R403 "CRCW040215K0JNED" 0402S 5465,880 r270 top value=15k
R404 "CRCW040247K0JNED" 0402S 5350,1365 r0 top value=47k
R405 "CRCW040215K0JNED" 0402S 5105,1035 r90 top value=15k
R406 "CRCW040227R0JNED" 0402S 5595,1090 r90 top value=27
R407 "CRCW040222R0JNED" 0402S 5595,1340 r270 top value=22
R408 "CRCW04021K50JNED" 0402S 5575,1260 r180 top value=1.5k
R409 "CRCW040222R0JNED" 0402S 5475,1340 r270 top value=22
R410 "CRCW040215K0JNED" 0402S 5105,935 r270 top value=15k
R411 "CRCW040215K0JNED" 0402S 5105,1135 r270 top value=15k
R412 "CRCW040215K0JNED" 0402S 5105,1235 r90 top value=15k
R413 "CRCW040222R0JNED" 0402S 5185,1110 r0 top value=22
R414 "CRCW040222R0JNED" 0402S 5185,1260 r0 top value=22
R415 "CRCW040222R0JNED" 0402S 5185,1060 r0 top value=22
R416 "CRCW040222R0JNED" 0402S 5185,910 r0 top value=22
R418 "RCG060310K0FKEA" 0603L 5275,1258.62 r90 top value=10.0k
RUSB "CRCW040233R0JNED" 0402S 5720,1540 r0 top value=33
S1 "B3U-1000P" SW_B3U-1000P 3450,250 r180 top
S2 "TL1015AF160QG" SW_TL1015AF160QG 3150.01,1149.99 r90 top
S3 "TL1015AF160QG" SW_TL1015AF160QG 3550.01,1149.99 r90 top
S4 "TL1015AF160QG" SW_TL1015AF160QG 3350.01,1149.99 r90 top
S5 "SS-13D16-VG 4 PA" SW_SS-13D16-VG 2750,750 r0 top
S201 "TL1015AF160QG" SW_TL1015AF160QG 4777.95,1660 r0 top
S202 "TL1015AF160QG" SW_TL1015AF160QG 5040,1660 r180 top
SH-J1 "60900213421" Wurth_60900213421 4050,1107.15 r90 top
SH-J2 "60900213421" Wurth_60900213421 3800,950 r180 top
SH-J3 "60900213421" Wurth_60900213421 3800,1055 r180 top
SH-J4 "60900213421" Wurth_60900213421 3800,1745 r180 top
SH-J5 "60900213421" Wurth_60900213421 3807.15,1650 r180 top
SH-J6 "60900213421" Wurth_60900213421 3807.15,1550 r180 top
SH-J7 "60900213421" Wurth_60900213421 3800,650 r180 top
SH-J8 "60900213421" Wurth_60900213421 3800,550 r180 top
SH-J9 "60900213421" Wurth_60900213421 750,150 r180 top
SH-J10 "60900213421" Wurth_60900213421 465,400 r180 top
SH-J11 "60900213421" Wurth_60900213421 465,600 r180 top
SH-J12 "60900213421" Wurth_60900213421 2000,400 r180 top
SH-J13 "60900213421" Wurth_60900213421 2000,650 r180 top
SH-J14 "60900213421" Wurth_60900213421 2250,650 r180 top
SH-J15 "60900213421" Wurth_60900213421 1642.85,1500 r180 top
SH-J16 "60900213421" Wurth_60900213421 1650,1600 r180 top
SH-J17 "60900213421" Wurth_60900213421 1650,1700 r180 top
SH-J18 "60900213421" Wurth_60900213421 1642.85,1800 r180 top
TP1 "5003" Keystone5003 1500,150 r90 top value=Orange
TP2 "5001" Keystone5001 1700,150 r90 top value=Black
U1 "MSP430FR6043IPN" PN0080A_N 2550,1650 r90 top
U4 "TPS22860DBVR" DBV0006A_N 950,445 r0 top
U5 "TPS61240DRVR" DRV0006A 1350,425 r0 top
U6 "TPS22860DBVR" DBV0006A_N 950,615 r0 top
U7 "TS5A9411DCKR" DCK0006A_N 580,1650 r0 top
U8 "TS5A9411DCKR" DCK0006A_N 740,1650 r180 top
U9 "SN74LVC2T45DCTR" DCT0008A_N 1100,1650 r0 top
U10 "OPA836IDBVT" DBV0006A_N 1050,1370 r270 top
U100 "MSP430F5528IRGCR" RGC0064B 4833.5,541.39 r90 top
U101 "TS5A21366RSER" RSE0008A 5568.5,255 r0 top
U102 "MSP430G2452IRSA16T" RSA0016B 5318.5,555 r180 top
U103 "TPD4E002DRL2" DRL0005A 4460,1020 r0 top
U200 "MSP430F5528IRGCR" RGC0064B 4680,1385 r270 top
U201 "TPD4E002DRL2" DRL0005A 4130,1400 r180 top
U202 "TPD4E002DRL2" DRL0005A 4120,1670 r270 top
U400 "TPD2E001DRLR" DRL0005A 5575,1460 r270 top
U401 "TUSB2046BIRHBR" RHB0032E 5425,1110 r270 top
U402 "TPS73533DRBR" DRB0008A 5235,1595 r90 top
Y1 "ABM3-8.000MHZ-D2Y-T" Abracon_ABM3 2610,1210 r0 top
Y2 "ABS07-32.768KHZ-9-T" XTAL_ABS07 2405,1240 r0 top
Y3 "AWSCR-8.00CV-T" Abracon_AWSCR-CV 1990,1295 r180 top
Y4 "ABLS-8.000MHZ-B4-T" XTAL_CSM-7X 1955,1070 r0 top
ZZ1 "This Assembly Note is for PCB labels only" AssemblyNoteLabel 55,7758 r0 top
ZZ2 "These assemblies are ESD sensitive, ESD precautions shall be observed." AssemblyNote 55,7649.11 r0 top
ZZ3 "These assemblies must be clean and free from flux and all contaminants. Use of no clean flux is not acceptable." AssemblyNote 55,7560.56 r0 top
ZZ4 "These assemblies must comply with workmanship standards IPC-A-610 Class 2, unless otherwise specified." AssemblyNote 55,7472 r0 top

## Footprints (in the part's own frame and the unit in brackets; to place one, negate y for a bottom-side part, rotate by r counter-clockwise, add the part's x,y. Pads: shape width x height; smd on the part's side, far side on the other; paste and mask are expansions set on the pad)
0402 [mm] "0402 from SM-752 data"
  rect 0.8x0.6 smd: 1(-0.6,0) 2(0.6,0)
  silkscreen extent -1.22,-0.52 1.22,0.52, body extent -0.55,-0.3 0.55,0.3, height 0.6
0402S [mil] "Based on C0402S footprint from PADS legacy"
  rect 15x24 smd: 1(-20,0) 2(20,0)
  body extent -22,-12 22,12, height 24
0603 [mm] "0603 from SM-752 data"
  rect 1x0.95 smd: 1(-0.8,0) 2(0.8,0)
  body extent -0.87,-0.47 0.87,0.47, height 1
0603L [mm] "0603 from SM-752 data"
  rect 0.8x0.85 smd: 1(-0.7,0) 2(0.7,0)
  silkscreen extent -0.07,-0.33 0.07,0.33, body extent -0.87,-0.47 0.87,0.47, height 1
0603M [mm] "0603 from SM-752 data"
  rect 1.2x1.05 smd: 1(-0.9,0) 2(0.9,0)
  body extent -0.87,-0.47 0.87,0.47, height 1
0603S [mil]
  rect 20x35 smd: 1(-30,0) 2(30,0)
  silkscreen extent -10,-17 10,17, body extent -34,-19 34,19, height 39
0805 [mm] "0805 from SM-752 data"
  rect 1.3x1.5 smd: 1(-0.85,0) 2(0.85,0)
  body extent -1.1,-0.72 1.1,0.72, height 1.45
0805_HV [mil] "0805 with 30mil clearance between pads"
  rect 50x63 smd: 1(-40,0) 2(40,0)
  body extent -43,-29 43,29, height 57
0805L [mm] "0805 from SM-752 data"
  rect 1.1x1.4 smd: 1(-0.75,0) 2(0.75,0)
  body extent -1.1,-0.72 1.1,0.72, height 1.45
Abracon_ABM3 [mm] "Abracon recommended land pattern 12.28.10"
  rect 1.9x2.4 smd: 1(-2.05,0) 2(2.05,0)
  silkscreen extent -2.67,-1.78 2.67,1.78, body extent -2.6,-1.7 2.6,1.7, height 1.3
Abracon_AWSCR-CV [mm] "SMD, 3-Leads, Body 3.7x3.1mm, Pitch 1.5mm"
  rrect14% 0.7x4.1 smd: 1(-1.5,0) 3(1.5,0)
  rrect10% 1x4.1 smd: 2(0,0)
  silkscreen extent -2.2,-2.4 2.2,2.4, body extent -1.85,-1.55 1.85,1.56, height 1.21
ADKOM_FH-1138P [mm] "TH, 38-Leads, Body 56x25.1mm"
  rrect50% 1.5x1.5 hole 0.9: 1(-12.7,24.13)
  round 1.5 hole 0.9: 2(-12.7,21.59) 3(-12.7,19.05) 4(-12.7,16.51) 5(-12.7,13.97) 6(-12.7,11.43) 7(-12.7,8.89) 8(-12.7,6.35) 9(-12.7,3.81) 10(-12.7,1.27) 11(-12.7,-1.27) 12(-12.7,-3.81) 13(-12.7,-6.35) 14(-12.7,-8.89) 15(-12.7,-11.43) 16(-12.7,-13.97) 17(-12.7,-16.51) 18(-12.7,-19.05) 19(-12.7,-21.59) 20(-12.7,-24.13) 21(12.7,-21.59) 22(12.7,-19.05) 23(12.7,-16.51) 24(12.7,-13.97) 25(12.7,-11.43) 26(12.7,-8.89) 27(12.7,-6.35) 28(12.7,-3.81) 29(12.7,-1.27) 30(12.7,1.27) 31(12.7,3.81) 32(12.7,6.35) 33(12.7,8.89) 34(12.7,11.43) 35(12.7,13.97) 36(12.7,16.51) 37(12.7,19.05) 38(12.7,21.59)
  silkscreen extent -12.55,-28.38 12.55,28, body extent -12.85,-28.38 12.85,27.5, height 3.1
AssemblyNote [mil] "Assembly Note"
AssemblyNoteLabel [mil] "Assembly Note for PCB Labels"
Bumpon_SJ5003Transparent [mil] "3M Hemispherical Bumpon transparent"
  round 1 on Mech4: 0(0,0)
  silkscreen extent -228,-228 228,228, body extent -219,-219 219,219, height 197
CE_Mark_5mm [mil] "Minimum text height for CE Mark"
  silkscreen extent -138,-98 138,98
CONN_PEC04DAAN [mm] "SULLINS"
  rect 1.65x1.65 hole 1.016 mask+0: 1(-3.81,-1.27)
  round 1.65 hole 1.016 mask+0: 2(-3.81,1.27) 3(-1.27,-1.27) 4(-1.27,1.27) 5(1.27,-1.27) 6(1.27,1.27) 7(3.81,-1.27) 8(3.81,1.27)
  silkscreen extent -6.18,-2.6 5.08,2.54, body extent -5.08,-2.54 5.08,2.54, height 8.38
CONN_SBH11-PBPC-D07-ST-BK [mm] "Sullins recommended land pattern"
  rect 1.65x1.65 hole 1.016 mask+0: 1(-7.62,-1.27)
  round 1.65 hole 1.016 mask+0: 2(-7.62,1.27) 3(-5.08,-1.27) 4(-5.08,1.27) 5(-2.54,-1.27) 6(-2.54,1.27) 7(0,-1.27) 8(0,1.27) 9(2.54,-1.27) 10(2.54,1.27) 11(5.08,-1.27) 12(5.08,1.27) 13(7.62,-1.27) 14(7.62,1.27)
  silkscreen extent -12.64,-5.08 12.64,4.7, body extent -12.64,-4.4 12.64,4.7, height 9.12
DBV0006A_N [mm] "SOT23, 6-Leads, Body 2.9x1.6mm, Pitch 0.95mm, Lead Span 2.8mm, IPC Medium Density"
  rrect17% 1x0.6 smd: 1(-1.375,0.95) 2(-1.375,0) 3(-1.375,-0.95) 4(1.375,-0.95) 5(1.375,0) 6(1.375,0.95)
  silkscreen extent -1.68,-1.55 0.5,1.55, body extent -1.42,-1.46 1.42,1.46, height 1.12
DCK0006A_N [mm] "SOT23, 6-Leads, Body 2x1.3mm, Pitch 0.65mm, Lead Span 2.1mm, IPC Medium Density"
  rrect25% 0.85x0.4 smd: 1(-1.125,0.65) 2(-1.125,0) 3(-1.125,-0.65) 4(1.125,-0.65) 5(1.125,0) 6(1.125,0.65)
  silkscreen extent -1.5,-1.09 0.51,1.09, body extent -1.14,-1 1.14,1, height 0.95
DCT0008A_N [mm] "TSOP, 8-Leads, Body 3x2.8mm, Pitch 0.65mm, IPC Medium Density"
  oval 1.05x0.4 smd: 1(-1.975,0.975) 2(-1.975,0.325) 3(-1.975,-0.325) 4(-1.975,-0.975) 5(1.975,-0.975) 6(1.975,-0.325) 7(1.975,0.325) 8(1.975,0.975)
  silkscreen extent -2.32,-1.57 1.4,1.58, body extent -2.01,-1.47 2.01,1.48, height 1.3
DRB0008A [mm] "SON, 8-Leads, Body 3x3mm, Pitch 0.65mm, Thermal Pad 1.75x1.5mm, TI Recommended"
  oval 0.6x0.3 smd: 1(-1.4,0.975) 2(-1.4,0.325) 3(-1.4,-0.325) 4(-1.4,-0.975) 5(1.4,-0.975) 6(1.4,-0.325) 7(1.4,0.325) 8(1.4,0.975)
  rect 1.5x1.75 smd paste-0.75: 9(0,0)
  Top Layer region: -0.465,-1.5 -0.465,-0.875 -0.75,-0.875 -0.75,0.875 -0.465,0.875 -0.465,1.5 -0.185,1.5 -0.185,0.875 0.185,0.875 0.185,1.5 0.465,1.5 0.465,0.875 0.75,0.875 0.75,-0.875 0.465,-0.875 0.465,-1.5 0.185,-1.5 0.185,-0.875 -0.185,-0.875 -0.185,-1.5
  silkscreen extent -1.73,-1.73 1.73,1.73, body extent -1.57,-1.57 1.58,1.58, height 1.01
DRL0005A [mm] "SOTFL, 5-Flat Leads, Body 1.2x1.6x0.6mm, Pitch 0.5mm, TI recommended"
  rect 0.5x0.3 smd: 1(-0.75,0.5) 2(-0.75,0) 3(-0.75,-0.5) 4(0.75,-0.5) 5(0.75,0.5)
  silkscreen extent -0.9,-0.95 0.9,0.95, body extent -0.85,-0.85 0.85,0.85, height 0.62
DRV0006A [mm] "SON, 6-Leads, Body 2x2mm, Pitch 0.65mm, Thermal Pad 1.6x1mm, TI Recommended"
  rrect33% 0.45x0.3 smd: 1(-0.975,0.65) 2(-0.975,0) 3(-0.975,-0.65) 4(0.975,-0.65) 5(0.975,0) 6(0.975,0.65)
  rrect14% 1x0.7 on Top Paste: 7(0,-0.45) 7(0,0.45)
  rrect10% 1x1.6 smd paste-0.5: 7(0,0)
  silkscreen extent -1.05,-1.2 1.05,1.2, body extent -1.05,-1.05 1.05,1.05, height 0.81
FCC_disclaimer [mil]
Fiducial10-30 [mm]
  round 1 smd mask+1: 1(0,0)
  Top Layer keep-out circle w1.678: c0,0 r0.75
Keystone5001 [mil] "For Keystone 500x miniature loop terminals"
  round 80 hole 40: 1(0,0)
  silkscreen extent -52,-52 52,52, body extent -49,-49 49,49, height 182
Keystone5003 [mil] "For Keystone 500x miniature loop terminals"
  round 80 hole 40: 1(0,0)
  silkscreen extent -52,-52 52,52, body extent -49,-49 49,49, height 182
Label_650x200 [mil] "Thermal Transfer Label"
  round 1 on Mech13: 0(0,0)
  silkscreen extent -325,-100 325,100, body extent -325,-100 325,100, height 1
LED_LTST-C190_Red [mm] "Lite-On"
  rect 0.8x0.8 smd: 1(-0.75,0) 2(0.75,0)
  silkscreen extent -1.1,-0.8 1.8,0.8, body extent -0.85,-0.45 0.85,0.45, height 0.9
LTST-C191_Green [mm] "Lite-On"
  rect 0.8x0.8 smd: 1(-0.75,0) 2(0.75,0)
  silkscreen extent -1.1,-0.8 1.8,0.8, body extent -0.85,-0.45 0.85,0.45, height 0.65
Molex_1051640001 [mm] "Receptacle, USB 2.0, Micro B, 5 Pos, 0.65mm Pitch, R/A, SMT"
  rrect22% 0.45x1.38 smd: 1(1.3,4.11) 2(0.65,4.11) 3(0,4.11) 4(-0.65,4.11) 5(-1.3,4.11)
  rrect7% 1.475x2.1 smd: 6(-2.462,3.75) 11(2.462,3.75)
  rrect100% 1.4x2.1 hole 0.6 slot 1.3 at 90 deg: 7(-3.95,1.45) 10(3.95,1.45)
  rrect7% 1.375x1.9 smd: 8(-0.937,1.45) 9(0.937,1.45)
  silkscreen extent 1.2,5.1 1.4,5.4, body extent -4.1,-0.7 4.1,4.47, height 2.45
Murata_CSTCR [mm] "Murata"
  rect 0.4x2.6 smd mask+0.051: 1(-1.5,0) 2(0,0) 3(1.5,0)
  Top Layer region: 1.1,-1.35 1.1,-0.85 1.9,-0.85 1.9,-1.35
  Top Layer region: 1.1,-1.35 1.1,-0.85 1.9,-0.85 1.9,-1.35
  Top Layer region: 1.1,0.8 1.9,0.8 1.9,1.3 1.1,1.3
  Top Layer region: -1.9,-1.35 -1.9,-0.85 -1.1,-0.85 -1.1,-1.35
  Top Layer region: -1.9,-1.35 -1.9,-0.85 -1.1,-0.85 -1.1,-1.35
  Top Layer region: -1.9,0.8 -1.1,0.8 -1.1,1.3 -1.9,1.3
  Top Layer region: -0.4,-1.35 -0.4,-0.85 0.4,-0.85 0.4,-1.35
  Top Layer region: -0.4,-1.35 -0.4,-0.85 0.4,-0.85 0.4,-1.35
  Top Layer region: -0.4,0.8 0.4,0.8 0.4,1.3 -0.4,1.3
  silkscreen extent -2.61,-1.56 2.32,1.08, body extent -2.3,-1.05 2.3,1.05, height 1.2
Net-Tie_50milWide_30milLong [mil] "50mil net tie, no solder mask opening, no solder paste"
  rect 30x50 smd paste-20 mask-20: 1(-15,0) 2(15,0)
PN0080A_N [mm] "QFP, 80-Leads, Body 12x12mm, Pitch 0.5mm, IPC Medium Density"
  oval 1.45x0.3 smd: 1(-6.725,4.75) 2(-6.725,4.25) 3(-6.725,3.75) 4(-6.725,3.25) 5(-6.725,2.75) 6(-6.725,2.25) 7(-6.725,1.75) 8(-6.725,1.25) 9(-6.725,0.75) 10(-6.725,0.25) 11(-6.725,-0.25) 12(-6.725,-0.75) 13(-6.725,-1.25) 14(-6.725,-1.75) 15(-6.725,-2.25) 16(-6.725,-2.75) 17(-6.725,-3.25) 18(-6.725,-3.75) 19(-6.725,-4.25) 20(-6.725,-4.75) 41(6.725,-4.75) 42(6.725,-4.25) 43(6.725,-3.75) 44(6.725,-3.25) 45(6.725,-2.75) 46(6.725,-2.25) 47(6.725,-1.75) 48(6.725,-1.25) 49(6.725,-0.75) 50(6.725,-0.25) 51(6.725,0.25) 52(6.725,0.75) 53(6.725,1.25) 54(6.725,1.75) 55(6.725,2.25) 56(6.725,2.75) 57(6.725,3.25) 58(6.725,3.75) 59(6.725,4.25) 60(6.725,4.75)
  oval 0.3x1.45 smd: 21(-4.75,-6.725) 22(-4.25,-6.725) 23(-3.75,-6.725) 24(-3.25,-6.725) 25(-2.75,-6.725) 26(-2.25,-6.725) 27(-1.75,-6.725) 28(-1.25,-6.725) 29(-0.75,-6.725) 30(-0.25,-6.725) 31(0.25,-6.725) 32(0.75,-6.725) 33(1.25,-6.725) 34(1.75,-6.725) 35(2.25,-6.725) 36(2.75,-6.725) 37(3.25,-6.725) 38(3.75,-6.725) 39(4.25,-6.725) 40(4.75,-6.725) 61(4.75,6.725) 62(4.25,6.725) 63(3.75,6.725) 64(3.25,6.725) 65(2.75,6.725) 66(2.25,6.725) 67(1.75,6.725) 68(1.25,6.725) 69(0.75,6.725) 70(0.25,6.725) 71(-0.25,6.725) 72(-0.75,6.725) 73(-1.25,6.725) 74(-1.75,6.725) 75(-2.25,6.725) 76(-2.75,6.725) 77(-3.25,6.725) 78(-3.75,6.725) 79(-4.25,6.725) 80(-4.75,6.725)
  silkscreen extent -6.85,-5.6 5.6,5.6, body extent -7,-7 7,7, height 1.56
RGC0064B [mm]
  oval 0.6x0.24 smd mask+0.07: 1(-4.4,3.75) 2(-4.4,3.25) 3(-4.4,2.75) 4(-4.4,2.25) 5(-4.4,1.75) 6(-4.4,1.25) 7(-4.4,0.75) 8(-4.4,0.25) 9(-4.4,-0.25) 10(-4.4,-0.75) 11(-4.4,-1.25) 12(-4.4,-1.75) 13(-4.4,-2.25) 14(-4.4,-2.75) 15(-4.4,-3.25) 16(-4.4,-3.75) 33(4.4,-3.75) 34(4.4,-3.25) 35(4.4,-2.75) 36(4.4,-2.25) 37(4.4,-1.75) 38(4.4,-1.25) 39(4.4,-0.75) 40(4.4,-0.25) 41(4.4,0.25) 42(4.4,0.75) 43(4.4,1.25) 44(4.4,1.75) 45(4.4,2.25) 46(4.4,2.75) 47(4.4,3.25) 48(4.4,3.75)
  oval 0.24x0.6 smd mask+0.07: 17(-3.751,-4.4) 18(-3.251,-4.4) 19(-2.751,-4.4) 20(-2.251,-4.4) 21(-1.75,-4.4) 22(-1.25,-4.4) 23(-0.75,-4.4) 24(-0.25,-4.4) 25(0.25,-4.4) 26(0.75,-4.4) 27(1.25,-4.4) 28(1.75,-4.4) 29(2.251,-4.4) 30(2.751,-4.4) 31(3.251,-4.4) 32(3.751,-4.4) 49(3.751,4.4) 50(3.251,4.4) 51(2.751,4.4) 52(2.251,4.4) 53(1.75,4.4) 54(1.25,4.4) 55(0.75,4.4) 56(0.25,4.4) 57(-0.25,4.4) 58(-0.75,4.4) 59(-1.25,4.4) 60(-1.75,4.4) 61(-2.251,4.4) 62(-2.751,4.4) 63(-3.251,4.4) 64(-3.751,4.4)
  rect 4.25x4.25 smd paste-2.112: 65(0,0)
  silkscreen extent -5.1,-5.1 5.1,5.1, body extent -4.57,-4.57 4.57,4.57, height 1.01
RHB0032E [mm] "QFN, 32-Leads, Body 5x5mm, Pitch 0.5mm, Thermal Pad 3.45x3.45mm, TI Recommended"
  oval 0.6x0.24 smd: 1(-2.4,1.75) 2(-2.4,1.25) 3(-2.4,0.75) 4(-2.4,0.25) 5(-2.4,-0.25) 6(-2.4,-0.75) 7(-2.4,-1.25) 8(-2.4,-1.75) 17(2.4,-1.75) 18(2.4,-1.25) 19(2.4,-0.75) 20(2.4,-0.25) 21(2.4,0.25) 22(2.4,0.75) 23(2.4,1.25) 24(2.4,1.75)
  oval 0.24x0.6 smd: 9(-1.75,-2.4) 10(-1.25,-2.4) 11(-0.75,-2.4) 12(-0.25,-2.4) 13(0.25,-2.4) 14(0.75,-2.4) 15(1.25,-2.4) 16(1.75,-2.4) 25(1.75,2.4) 26(1.25,2.4) 27(0.75,2.4) 28(0.25,2.4) 29(-0.25,2.4) 30(-0.75,2.4) 31(-1.25,2.4) 32(-1.75,2.4)
  rect 3.45x3.45 smd paste-1.725: 33(0,0)
  silkscreen extent -2.72,-2.73 2.72,2.73, body extent -2.57,-2.57 2.58,2.58, height 1.01
RSA0016B [mm] "QFN, 16-Leads, Body 4x4mm, Pitch 0.65mm, Thermal Pad 2.7x2.7mm, TI Recommended"
  oval 0.6x0.3 smd: 1(-1.9,0.975) 2(-1.9,0.325) 3(-1.9,-0.325) 4(-1.9,-0.975) 9(1.9,-0.975) 10(1.9,-0.325) 11(1.9,0.325) 12(1.9,0.975)
  oval 0.3x0.6 smd: 5(-0.975,-1.9) 6(-0.325,-1.9) 7(0.325,-1.9) 8(0.975,-1.9) 13(0.975,1.9) 14(0.325,1.9) 15(-0.325,1.9) 16(-0.975,1.9)
  rect 2.7x2.7 smd paste-1.35: 17(0,0)
  Top Layer keep-out region: -2,1.5 -1.5,1.5 -1.5,2 -2,2
  silkscreen extent -2.2,-2.2 2.2,2.2, body extent -2.05,-2.05 2.05,2.05, height 1.01
RSE0008A [mm] "QFN, 8-Leads, Body 1.5x1.5mm, Pitch 0.5mm, TI Recommended"
  rrect40% 0.55x0.25 smd: 1(-0.675,0.5) 3(-0.675,-0.5) 5(0.675,-0.5) 7(0.675,0.5)
  rrect50% 0.55x0.2 smd: 2(-0.675,0) 6(0.675,0)
  rrect33% 0.3x0.6 smd: 4(0,-0.65) 8(0,0.65)
  silkscreen extent -1.02,-0.92 0.77,0.93, body extent -0.75,-0.75 0.75,0.75, height 0.6
Samtec_TSW-110-07-x-D [mm] "Header, 10x2, 2.54mm, TH"
  rect 1.55x1.55 hole 1.02: 1(-1.27,11.43)
  round 1.55 hole 1.02: 2(1.27,11.43) 3(-1.27,8.89) 4(1.27,8.89) 5(-1.27,6.35) 6(1.27,6.35) 7(-1.27,3.81) 8(1.27,3.81) 9(-1.27,1.27) 10(1.27,1.27) 11(-1.27,-1.27) 12(1.27,-1.27) 13(-1.27,-3.81) 14(1.27,-3.81) 15(-1.27,-6.35) 16(1.27,-6.35) 17(-1.27,-8.89) 18(1.27,-8.89) 19(-1.27,-11.43) 20(1.27,-11.43)
  silkscreen extent -2.9,-12.7 2.54,12.7, body extent -2.54,-12.7 2.54,12.7, height 8.38
SOT-23 [mm] "SOT23, 3-Leads, Body 2.9x1.3mm, Pitch 0.95mm, Lead Span 2.5mm, IPC Medium Density"
  rrect50% 1x0.6 smd: 1(-1.2,0.95) 2(-1.2,-0.95) 3(1.2,0)
  silkscreen extent -1.63,-1.5 0.7,1.5, body extent -1.16,-1.45 1.21,1.45, height 1
SOT-323 [mm] "Zetex recommended land pattern.  March 2007"
  rect 0.8x0.6 smd: 1(-0.8,0.65) 2(-0.8,-0.65) 3(0.8,0)
  silkscreen extent -1.14,-1.22 0.77,1.22, body extent -1.13,-1.13 1.12,1.12, height 1.13
Sullins_PxC02DAAN [mm] "Header, 2.54mm, 2x2, TH"
  rect 1.7x1.7 hole 1.2: 1(-1.27,1.27)
  round 1.7 hole 1.2: 2(1.27,1.27) 3(-1.27,-1.27) 4(1.27,-1.27)
  silkscreen extent -2.61,-2.8 2.61,3.2, body extent -2.61,-2.8 2.61,2.8, height 8.58
Sullins_xxC07SAAN [mm] "Header, 2.54 mm, 7x1, TH"
  rect 1.55x1.55 hole 1.016: 1(-7.62,0)
  round 1.55 hole 1.016: 2(-5.08,0) 3(-2.54,0) 4(0,0) 5(2.54,0) 6(5.08,0) 7(7.62,0)
  silkscreen extent -8.89,-1.27 8.89,1.7, body extent -8.89,-1.27 8.89,1.27, height 8.38
SW_B3U-1000P [mm] "OMRON"
  rect 0.8x1.7 smd: 1(-1.7,0) 2(1.7,0)
  silkscreen extent -1.5,-1.25 1.5,1.25, body extent -1.5,-1.25 1.5,1.25, height 1.75
SW_SS-13D16-VG [mm] "TH, 4-Leads, Body 12.6x4.3mm, Pitch 2mm"
  rect 1.3x1.3 hole 0.8: 1(-4,0)
  round 1.3 hole 0.8: 2(0,0) 3(2,0) 4(4,0)
  round 1.75 hole 1.25: S1(-6.1,0) S2(6.1,0)
  silkscreen extent -6.3,-2.75 6.3,2.15, body extent -6.3,-2.15 6.3,2.15, height 8.7
SW_TL1015AF160QG [mm] "E-Switch"
  rect 0.95x1.4 smd: 1(-2.1,0) 2(2.1,0)
  silkscreen extent -2,-1.5 2,1.5, body extent -2.3,-1.5 2.3,1.5, height 2
TI_Stacked_Overlay_Small [mil]
  silkscreen extent -418,-98 418,98
TRIM_3224W [mm] "BOURNS"
  rect 1.6x1.3 smd: 1(-1.45,1.25) 3(-1.45,-1.25)
  rect 1.6x2 smd: 2(1.45,0)
  silkscreen extent -1.9,-2.6 1.9,2.6, body extent -1.8,-2.5 1.8,2.5, height 5.31
TSW-105-07-G-D [mm] "Samtec 100mil, 2x5, 230 mil above insulator"
  rrect6% 1.65x1.65 hole 1.016: 1(-5.08,-1.27)
  round 1.65 hole 1.016: 2(-5.08,1.27) 3(-2.54,-1.27) 4(-2.54,1.27) 5(0,-1.27) 6(0,1.27) 7(2.54,-1.27) 8(2.54,1.27) 9(5.08,-1.27) 10(5.08,1.27)
  silkscreen extent -7.37,-2.54 6.35,2.54, body extent -6.35,-2.54 6.35,2.54, height 8.38
TSW-106-07-G-D [mm] "Samtec 100mil, 2x6, 230 mil above insulator"
  rrect6% 1.65x1.65 hole 1.016: 1(-6.35,-1.27)
  round 1.65 hole 1.016: 2(-6.35,1.27) 3(-3.81,-1.27) 4(-3.81,1.27) 5(-1.27,-1.27) 6(-1.27,1.27) 7(1.27,-1.27) 8(1.27,1.27) 9(3.81,-1.27) 10(3.81,1.27) 11(6.35,-1.27) 12(6.35,1.27)
  silkscreen extent -8.64,-2.54 7.62,2.54, body extent -7.62,-2.54 7.62,2.54, height 8.38
WEEE_Minimum [mil] "WEEElie bin"
  silkscreen extent -95,-172 99,104
Wurth_60900213421 [mil] "Shunt, 2.54mm, Black"
  round 1 on Mech3: 0(0,0)
  body extent -98,-48 98,48, height 338
WURTH_61300211121 [mm] "Header, 2.54mm, 2x1, TH"
  rect 1.65x1.65 hole 1.15: 1(-1.27,0)
  round 1.65 hole 1.15: 2(1.27,0)
  silkscreen extent -2.54,-1.27 2.54,1.6, body extent -2.54,-1.27 2.54,1.27, height 8.54
WURTH_61300311121 [mm] "Header, 2.54mm, 3x1, TH"
  rect 1.65x1.65 hole 1.15: 1(-2.54,0)
  round 1.65 hole 1.15: 2(0,0) 3(2.54,0)
  silkscreen extent -3.81,-1.27 3.81,1.6, body extent -3.81,-1.27 3.81,1.27, height 8.54
XTAL_ABS07 [mm] "ABRACON"
  rect 1.1x1.9 smd: 1(-1.25,0) 2(1.25,0)
  silkscreen extent -0.4,-1 0.4,1, body extent -1.65,-0.8 1.65,0.8, height 0.9
XTAL_CSM-7X [mm] "ECS"
  rect 5.5x2 smd: 1(-4.75,0) 2(4.75,0)
  silkscreen extent -6.2,-2.5 6.2,2.5, body extent -5.95,-2.4 5.95,2.4, height 4.3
